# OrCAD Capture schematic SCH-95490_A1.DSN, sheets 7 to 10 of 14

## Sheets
7 07 MCU_LINK: size C
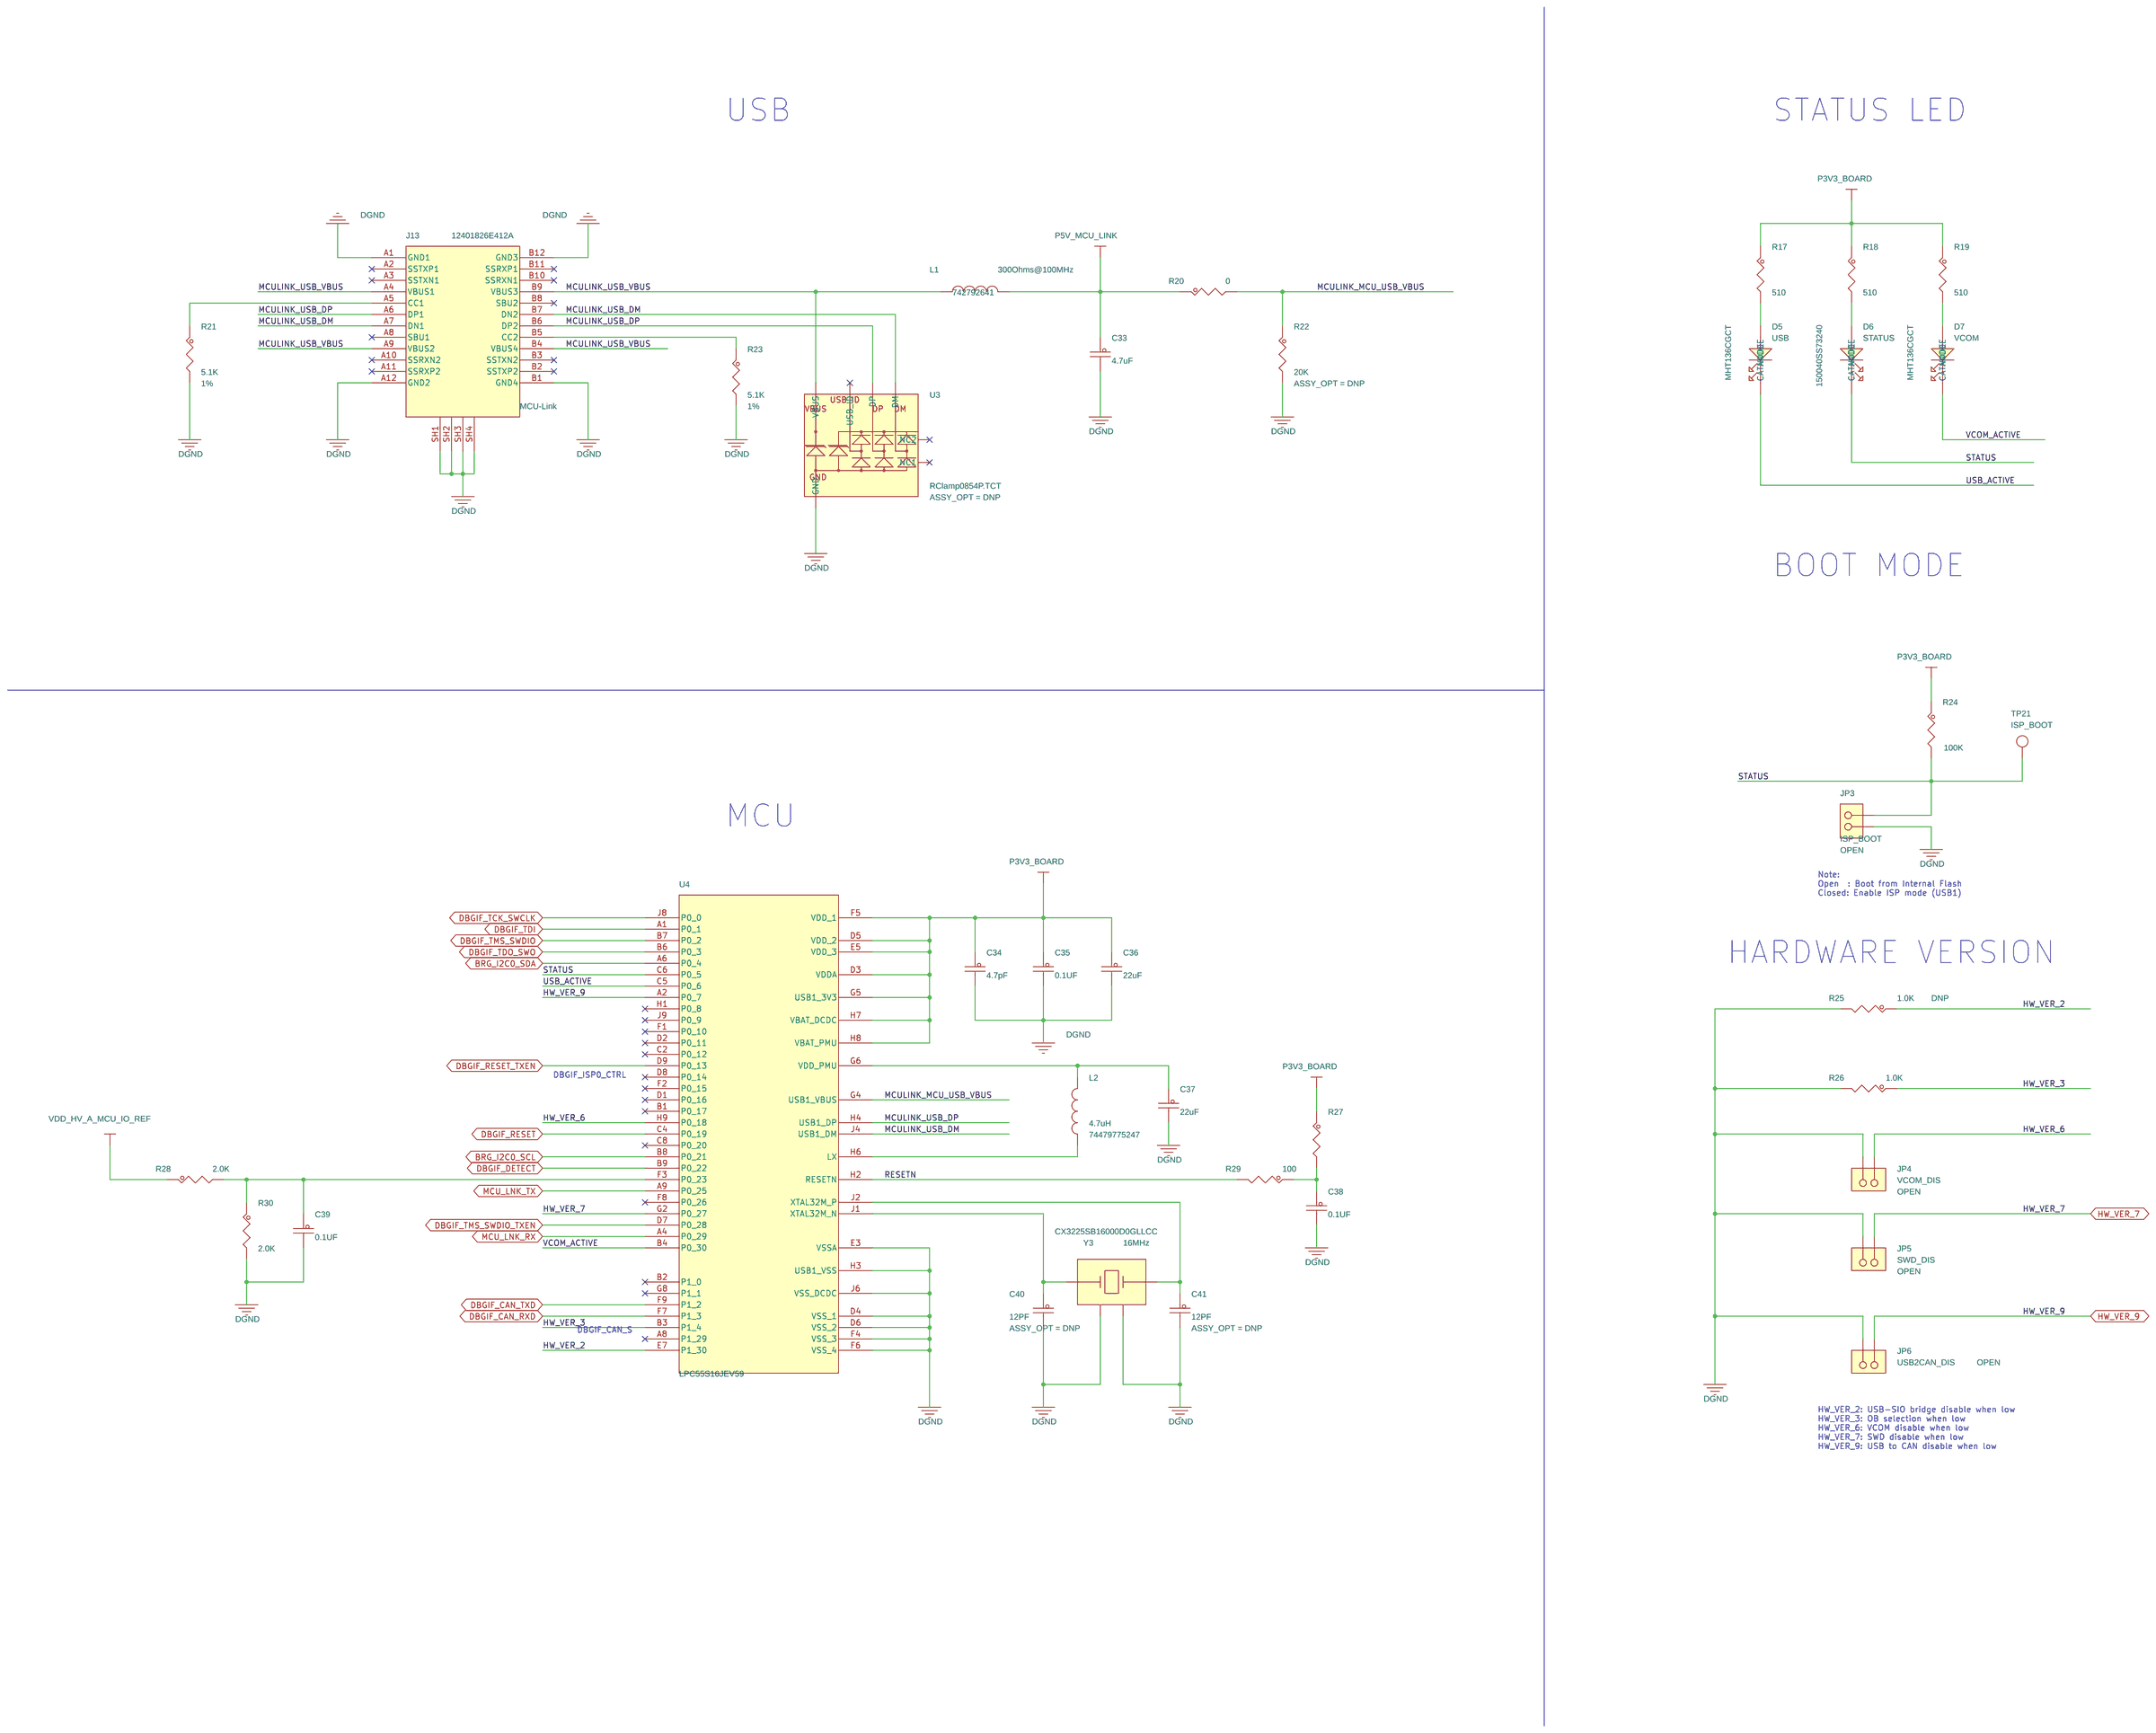
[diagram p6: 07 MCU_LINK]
8 08 MCU_LINK_DEBUG: size C
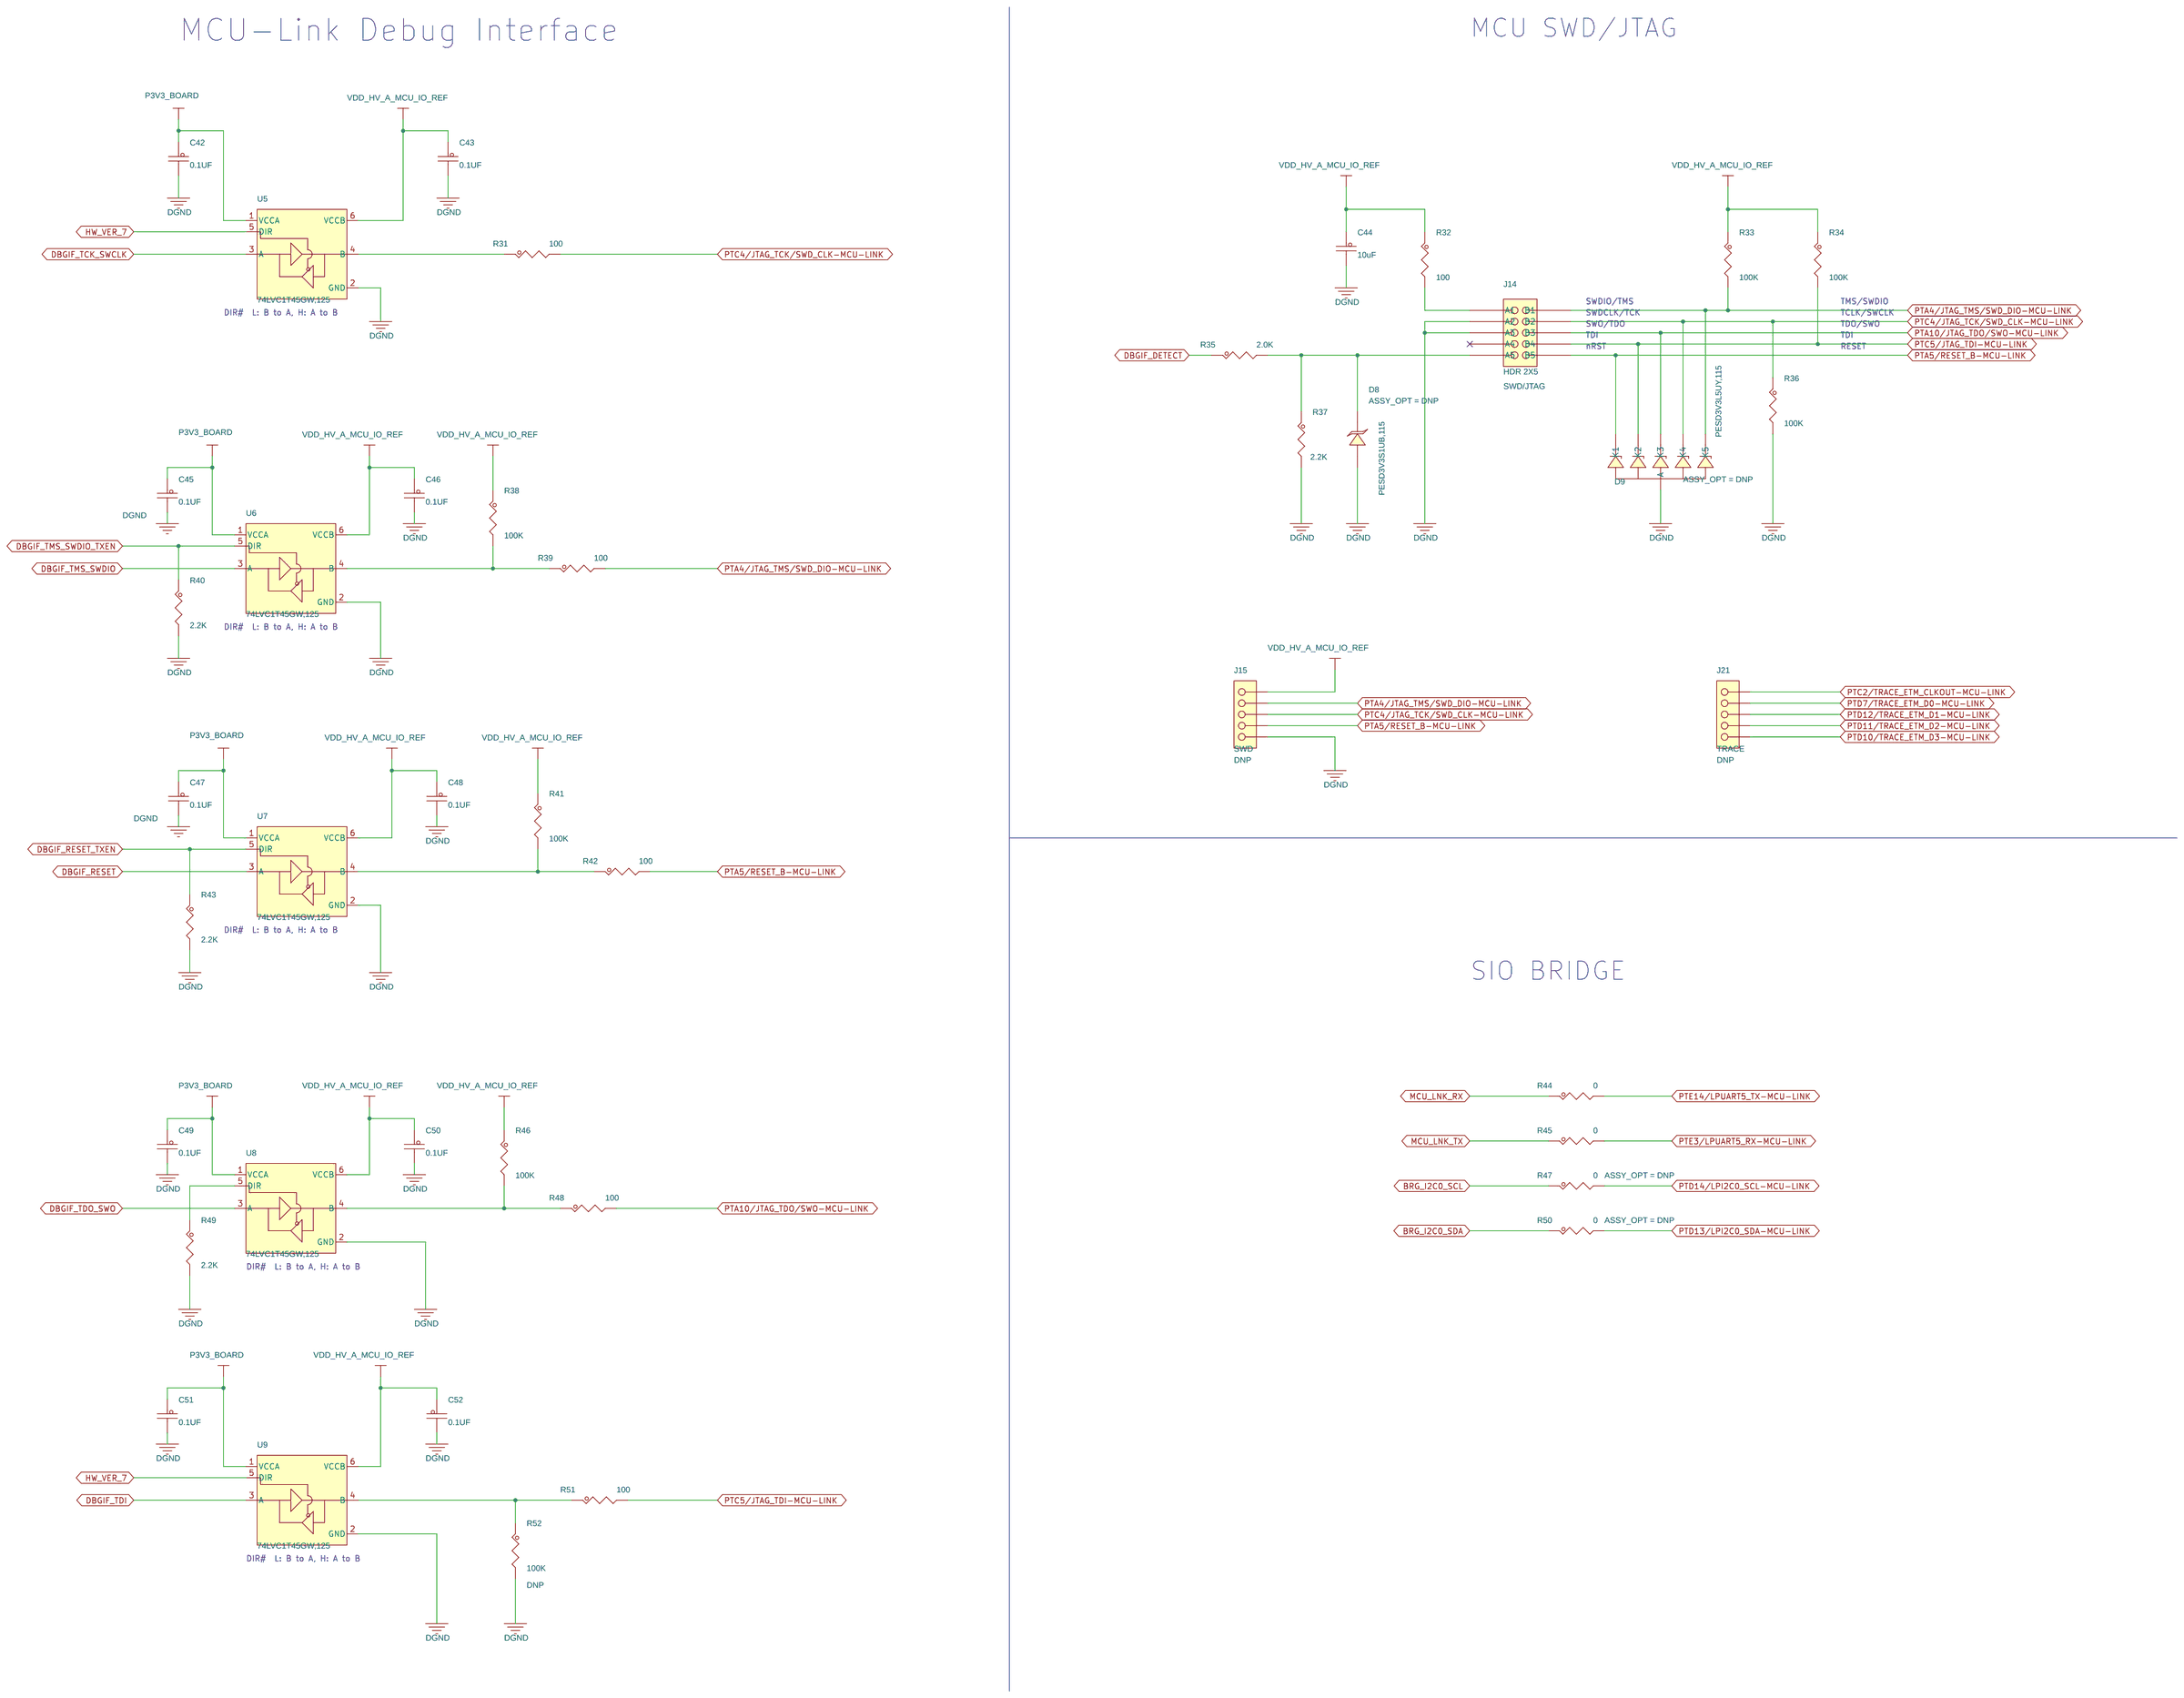
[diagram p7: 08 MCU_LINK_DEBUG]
9 09 ETHERNET: size C
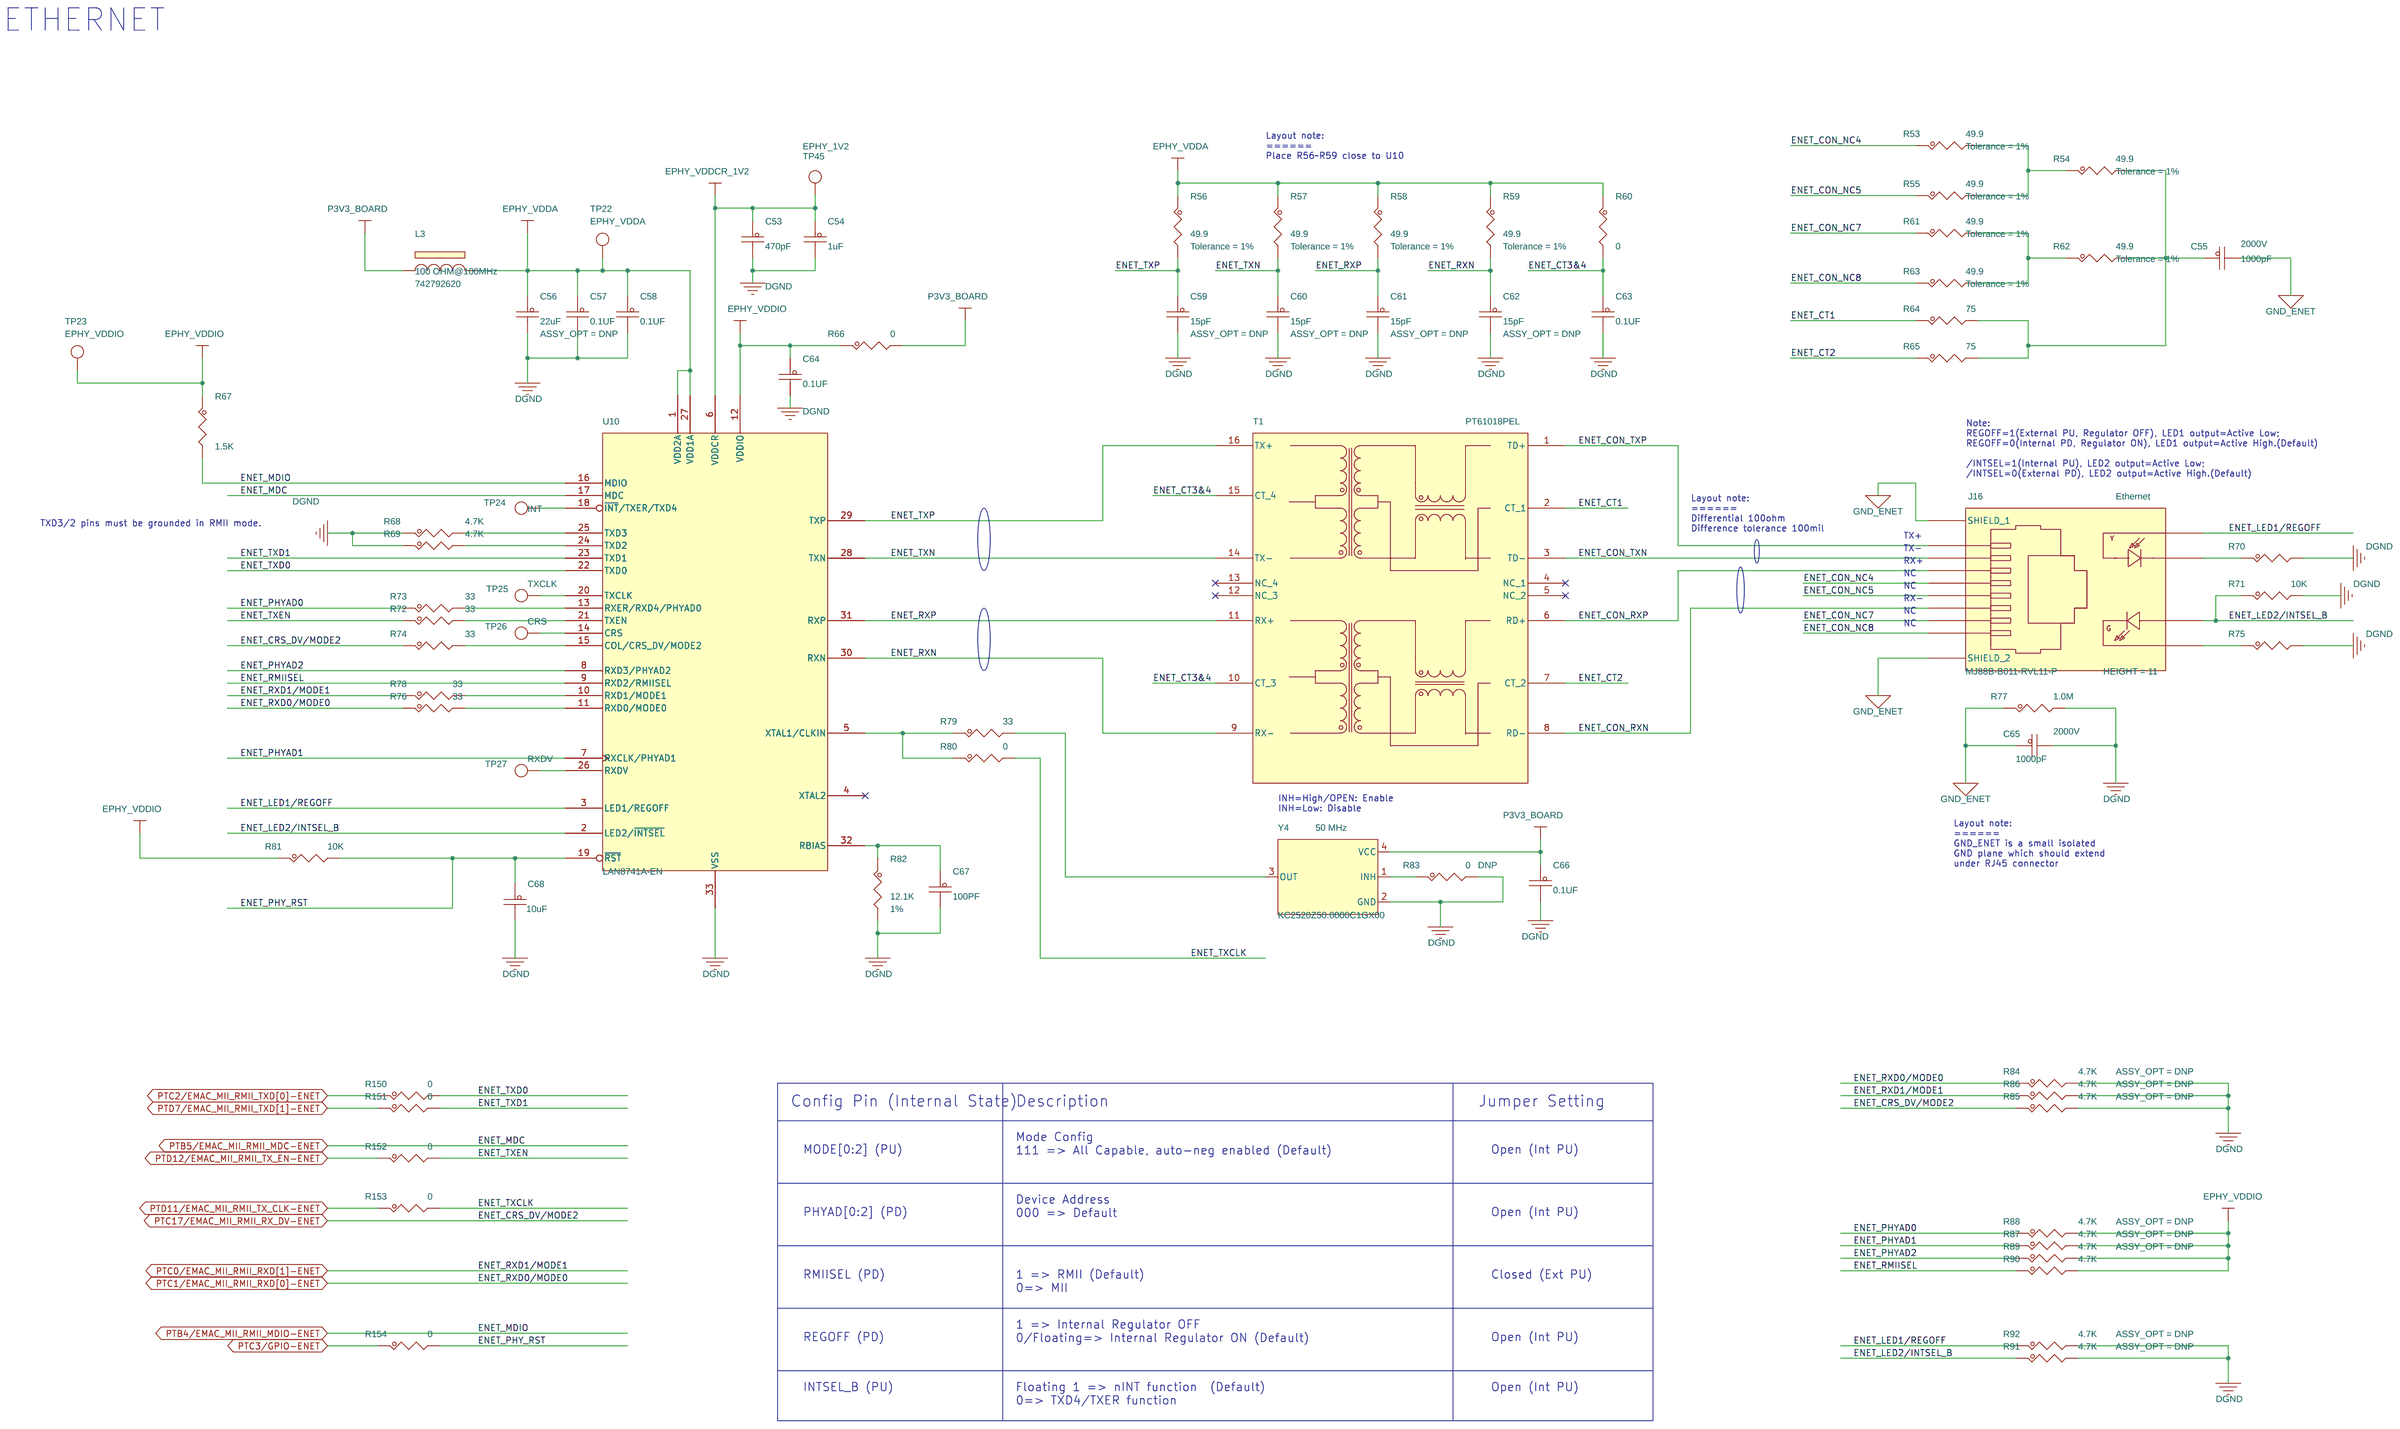
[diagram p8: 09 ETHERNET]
10 10 CAN: size C
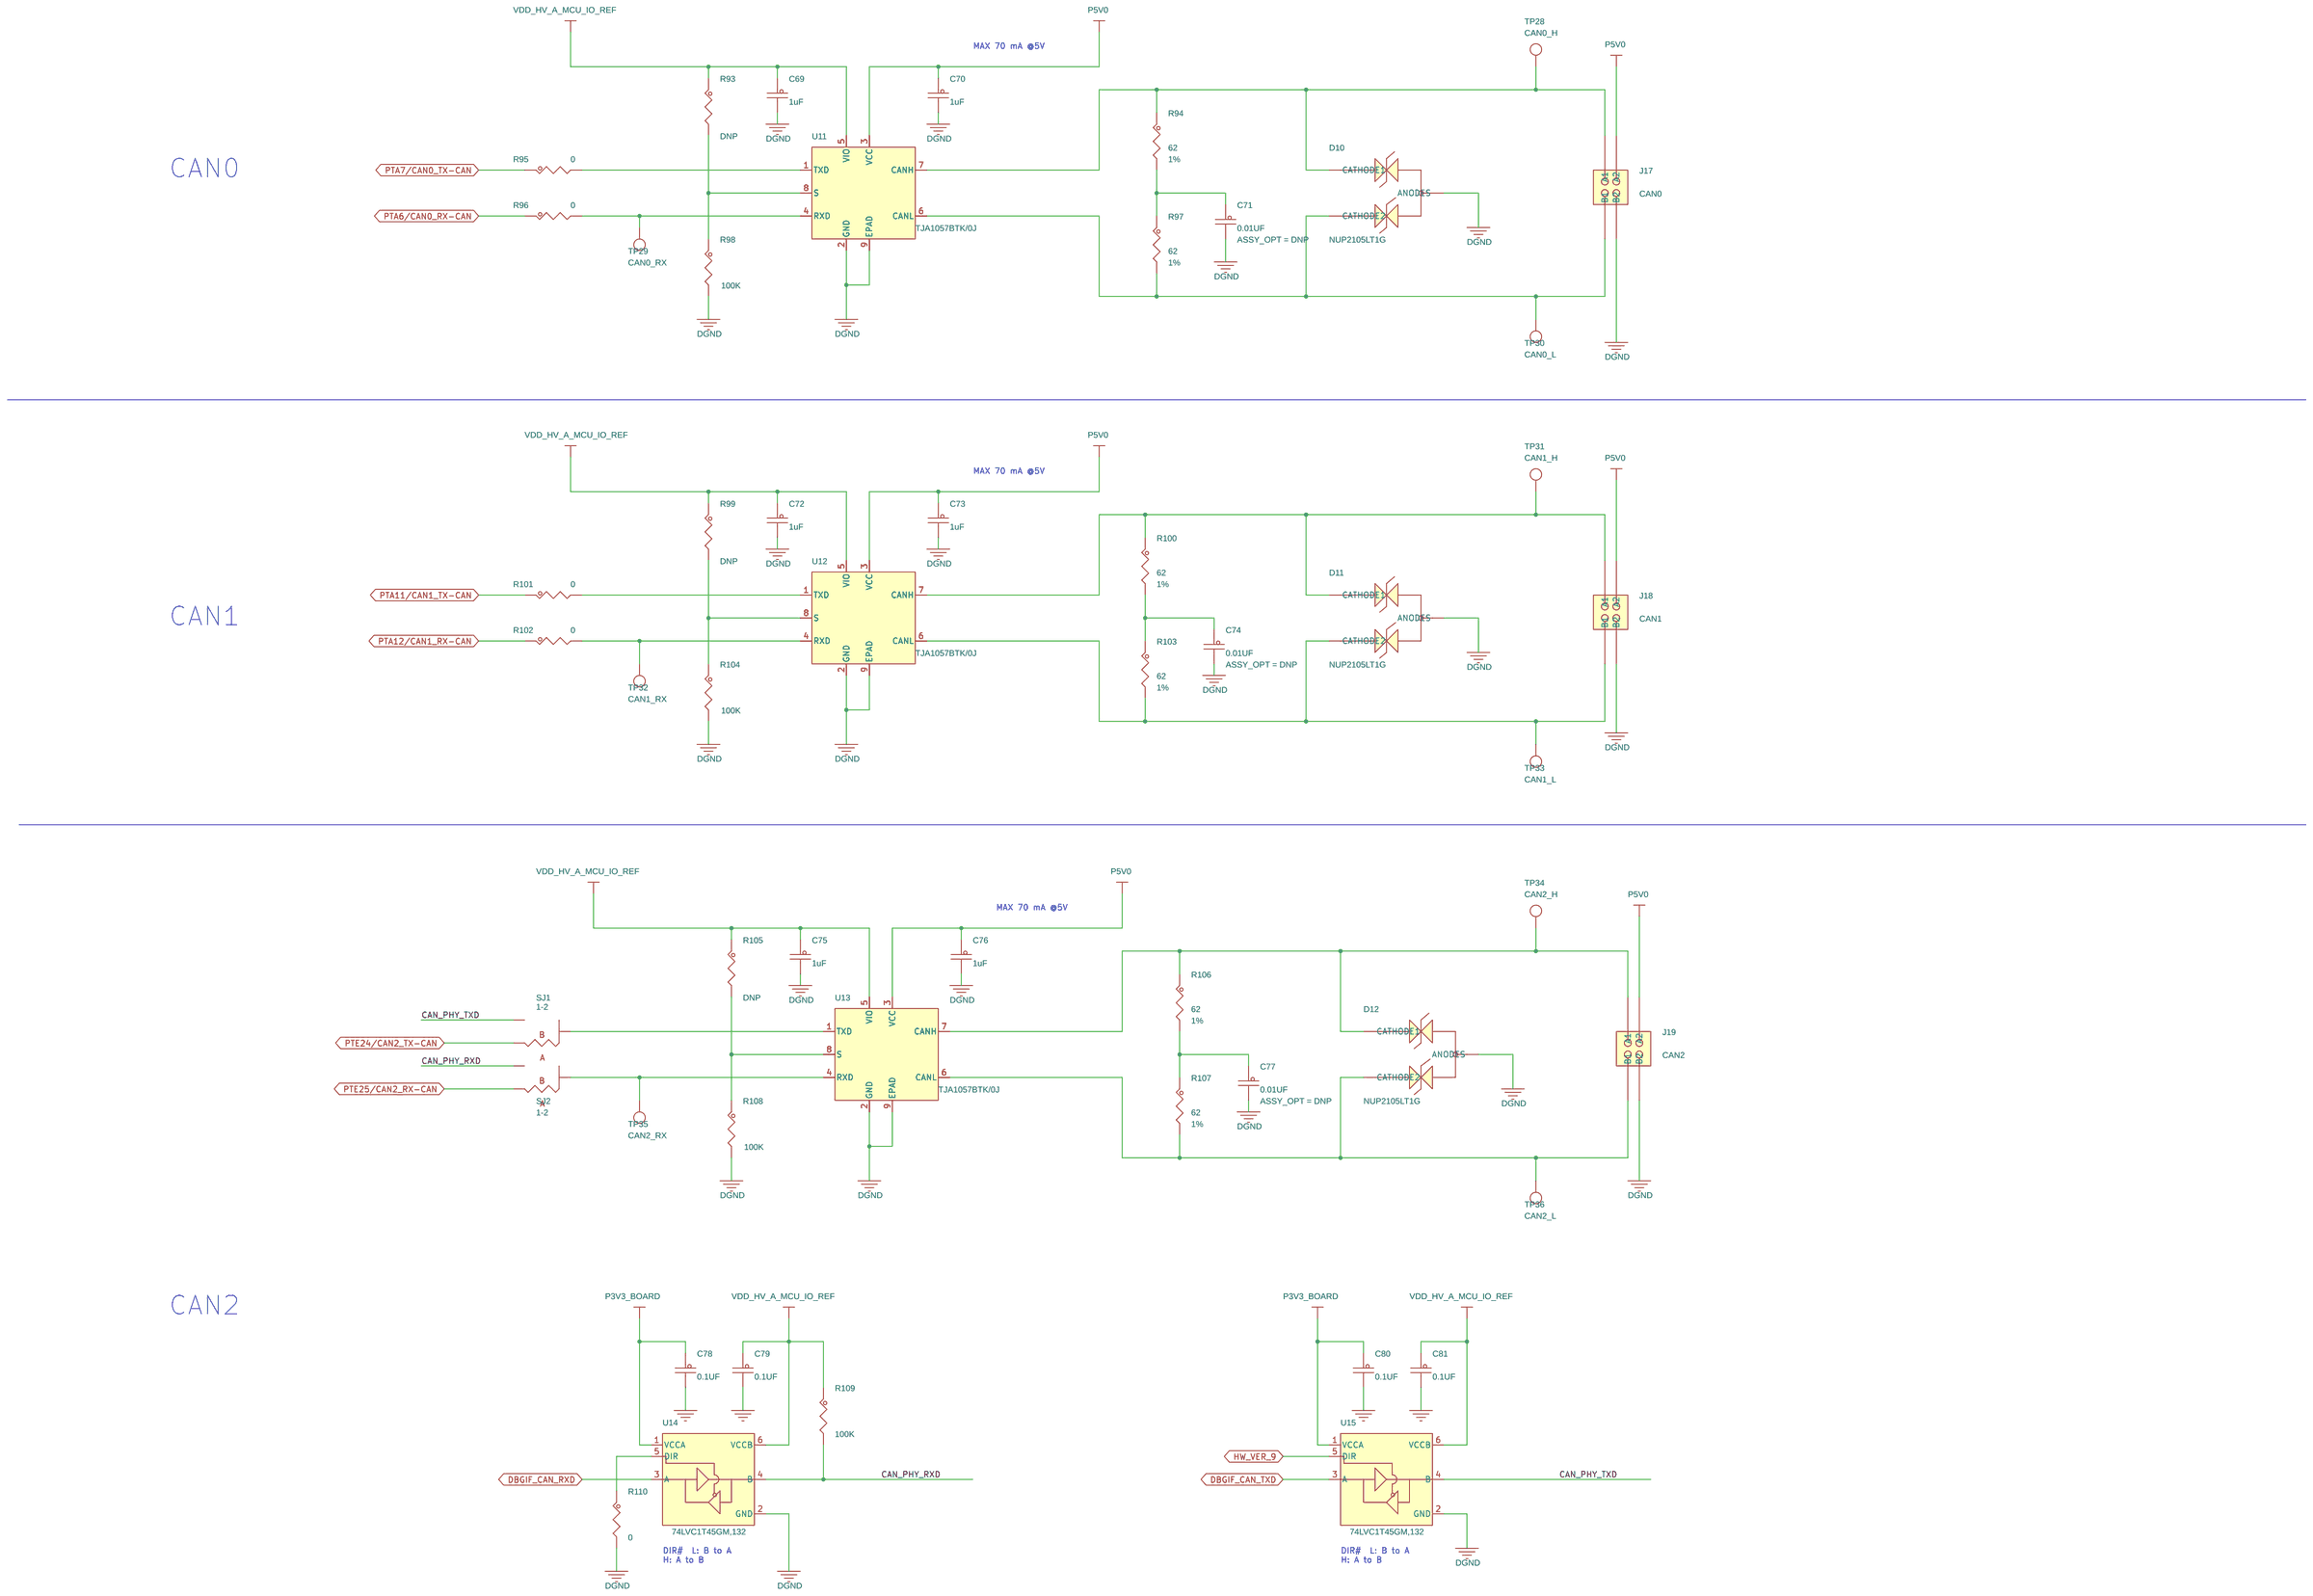
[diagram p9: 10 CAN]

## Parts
sheet 07 MCU_LINK
C33  4.7uF  [CC0603_OV]
C34  4.7pF  [CC0402_25]
C35  0.1UF  [CC0402_25]
C36  22uF  [CC0603_OV]
C37  22uF  [CC0603_OV]
C38  0.1UF  [CC0402_25]
C39  0.1UF  [CC0402_25]
C40  12PF  [CC0402_25]
C41  12PF  [CC0402_25]
D5  YEL-GRN  [led_1x0p6_sm]
D6  RED LED  [led_1p1_1p1x0p6_sm]
D7  YEL-GRN  [led_1x0p6_sm]
J13  USB_TYPE_C  [usb24_type_c_10p5x9p18mm_ra_smt]
JP3  HDR1X2  [hdr1x2_5p48x2p69]
JP4  HDR1X2  [hdr1x2_5p48x2p69]
JP5  HDR1X2  [hdr1x2_5p48x2p69]
JP6  HDR1X2  [hdr1x2_5p48x2p69]
L1  300Ohms@100MHz  [ind_1p8x1mm_sm]
L2  4.7uH  [ind_2p3x1p4_1_sm]
R17  510  [RC0402_25]
R18  510  [RC0402_25]
R19  510  [RC0402_25]
R20  0  [RC0603_OV]
R21  5.1K  [RC0402_25]
R22  20K  [RC0402_25]
R23  5.1K  [RC0402_25]
R24  100K  [RC0402_25]
R25  1.0K  [RC0402_25]
R26  1.0K  [RC0402_25]
R27  10K  [RC0402_25]
R28  2.0K  [RC0402_25]
R29  100  [RC0402_25]
R30  2.0K  [RC0402_25]
TP21  TEST POINT  [tpad_040-fct]
U3  RClamp0854P.TCT  [slp1616p6]
U4  LPC55S16JEV59  [pbga59_0p4_4x4mm]
Y3  16MHz  [xtal4_cx3225ca_sm]
sheet 08 MCU_LINK_DEBUG
C42  0.1UF  [CC0402_25]
C43  0.1UF  [CC0402_25]
C44  10uF  [CC0603_OV]
C45  0.1UF  [CC0402_25]
C46  0.1UF  [CC0402_25]
C47  0.1UF  [CC0402_25]
C48  0.1UF  [CC0402_25]
C49  0.1UF  [CC0402_25]
C50  0.1UF  [CC0402_25]
C51  0.1UF  [CC0402_25]
C52  0.1UF  [CC0402_25]
D8  PESD3V3S1UB  [sod523]
D9  PESD3V3L5UY  [sot-363_0p65_smt]
J14  HDR 2X5  [hdr_5x2_ftsh_th_nsp_a]
J15  HDR_1X5  [con1x5_2p54_th_ra]
J21  HDR 1X5  [hdr1x5_2p54_2p7x12p9_th]
R31  100  [RC0402_25]
R32  100  [RC0402_25]
R33  100K  [RC0402_25]
R34  100K  [RC0402_25]
R35  2.0K  [RC0402_25]
R36  100K  [RC0402_25]
R37  2.2K  [RC0402_25]
R38  100K  [RC0402_25]
R39  100  [RC0402_25]
R40  2.2K  [RC0402_25]
R41  100K  [RC0402_25]
R42  100  [RC0402_25]
R43  2.2K  [RC0402_25]
R44  0  [RC0603_OV]
R45  0  [RC0603_OV]
R46  100K  [RC0402_25]
R47  0  [RC0603_OV]
R48  100  [RC0402_25]
R49  2.2K  [RC0402_25]
R50  0  [RC0603_OV]
R51  100  [RC0402_25]
R52  100K  [RC0402_25]
U5  74LVC1T45GW,125  [SOT-363_0P65_SMT]
U6  74LVC1T45GW,125  [SOT-363_0P65_SMT]
U7  74LVC1T45GW,125  [SOT-363_0P65_SMT]
U8  74LVC1T45GW,125  [SOT-363_0P65_SMT]
U9  74LVC1T45GW,125  [SOT-363_0P65_SMT]
sheet 09 ETHERNET
C53  470pF  [CC0402_25]
C54  1uF  [CC0402_25]
C55  1000pF  [CC1206_OV]
C56  22uF  [CC0603_OV]
C57  0.1UF  [CC0402_25]
C58  0.1UF  [CC0402_25]
C59  15pF  [CC0402_25]
C60  15pF  [CC0402_25]
C61  15pF  [CC0402_25]
C62  15pF  [CC0402_25]
C63  0.1UF  [CC0402_25]
C64  0.1UF  [CC0402_25]
C65  1000pF  [CC1206_OV]
C66  0.1UF  [CC0402_25]
C67  100PF  [CC0402_25]
C68  10uF  [CC0603_OV]
J16  RJ45X2_LEDYG  [con12p_1p02_16p48x15p5_ra_th]
L3  100 OHM@100MHz  [ind_1p8x1mm_sm]
R53  49.9  [RC0402_25]
R54  49.9  [RC0402_25]
R55  49.9  [RC0402_25]
R56  49.9  [RC0402_25]
R57  49.9  [RC0402_25]
R58  49.9  [RC0402_25]
R59  49.9  [RC0402_25]
R60  0  [RC0603_OV]
R61  49.9  [RC0402_25]
R62  49.9  [RC0402_25]
R63  49.9  [RC0402_25]
R64  75  [RC0402_25]
R65  75  [RC0402_25]
R66  0  [RC0603_OV]
R67  1.5K  [RC0402_25]
R68  4.7K  [RC0402_25]
R69  4.7K  [RC0402_25]
R70  470  [RC0402_25]
R71  10K  [RC0402_25]
R72  33  [RC0402_25]
R73  33  [RC0402_25]
R74  33  [RC0402_25]
R75  470  [RC0402_25]
R76  33  [RC0402_25]
R77  1.0M  [RC0805_OV]
R78  33  [RC0402_25]
R79  33  [RC0402_25]
R80  0  [RC0603_OV]
R81  10K  [RC0402_25]
R82  12.1K  [RC0402_25]
R83  0  [RC0603_OV]
R84  4.7K  [RC0402_25]
R85  4.7K  [RC0402_25]
R86  4.7K  [RC0402_25]
R87  4.7K  [RC0402_25]
R88  4.7K  [RC0402_25]
R89  4.7K  [RC0402_25]
R90  4.7K  [RC0402_25]
R91  4.7K  [RC0402_25]
R92  4.7K  [RC0402_25]
R150  0  [RC0603_OV]
R151  0  [RC0603_OV]
R152  0  [RC0603_OV]
R153  0  [RC0603_OV]
R154  0  [RC0603_OV]
T1  PT61018PEL  [xfmr16_1p27_13p05x7p15]
TP22  TEST POINT  [tpad_040-fct]
TP23  TEST POINT  [tpad_040-fct]
TP24  TPAD_030  [TPAD_030]
TP25  TPAD_030  [TPAD_030]
TP26  TPAD_030  [TPAD_030]
TP27  TPAD_030  [TPAD_030]
TP45  TEST POINT  [tpad_040-fct]
U10  LAN8741A-EN  [QFN32EP]
Y4  50 MHz  [osc4_2p6x2p1_sm]
sheet 10 CAN
C69  1uF  [CC0402_25]
C70  1uF  [CC0402_25]
C71  0.01UF  [CC0402_25]
C72  1uF  [CC0402_25]
C73  1uF  [CC0402_25]
C74  0.01UF  [CC0402_25]
C75  1uF  [CC0402_25]
C76  1uF  [CC0402_25]
C77  0.01UF  [CC0402_25]
C78  0.1UF  [CC0402_25]
C79  0.1UF  [CC0402_25]
C80  0.1UF  [CC0402_25]
C81  0.1UF  [CC0402_25]
D10  NUP2105L  [sot-23]
D11  NUP2105L  [sot-23]
D12  NUP2105L  [sot-23]
J17  HDR 2X2  [hdr202_100_th]
J18  HDR 2X2  [hdr202_100_th]
J19  HDR 2X2  [hdr202_100_th]
R93  10K  [RC0402_25]
R94  62  [RC0805_OV]
R95  0  [RC0603_OV]
R96  0  [RC0603_OV]
R97  62  [RC0805_OV]
R98  100K  [RC0402_25]
R99  10K  [RC0402_25]
R100  62  [RC0805_OV]
R101  0  [RC0603_OV]
R102  0  [RC0603_OV]
R103  62  [RC0805_OV]
R104  100K  [RC0402_25]
R105  10K  [RC0402_25]
R106  62  [RC0805_OV]
R107  62  [RC0805_OV]
R108  100K  [RC0402_25]
R109  100K  [RC0402_25]
R110  0  [RC0603_OV]
SJ1  3 PIN 0402 JUMPER  [3pin_0402x2_a]
SJ2  3 PIN 0402 JUMPER  [3pin_0402x2_a]
TP28  TEST POINT  [tpad_040-fct]
TP29  TPAD_030  [TPAD_030]
TP30  TEST POINT  [tpad_040-fct]
TP31  TEST POINT  [tpad_040-fct]
TP32  TPAD_030  [TPAD_030]
TP33  TEST POINT  [tpad_040-fct]
TP34  TEST POINT  [tpad_040-fct]
TP35  TPAD_030  [TPAD_030]
TP36  TEST POINT  [tpad_040-fct]
U11  TJA1057BTK  [son8_0p65_3p15x3p15]
U12  TJA1057BTK  [son8_0p65_3p15x3p15]
U13  TJA1057BTK  [son8_0p65_3p15x3p15]
U14  74LVC1T45GM,132  [udfn6_1x1p5mm]
U15  74LVC1T45GM,132  [udfn6_1x1p5mm]

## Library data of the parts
C33 = CAP_NP: CAP CER 4.7uF 10V 20% X5R 0603; 3D_Mechanical_Footprint_File: http://fcl.am.freescale.net/ALLEGRO/step/cc0603_ov.STEP; AGILE_PN: 150-81893; CAD_APPROVED: Yes; FPLIST: CC0603_OV,CC0603,0603_CC; HEIGHT: 0.87; MFG_NAME01: WURTH ELEKTRONIK; MFG_PN01: 885012106012; Package Size: 0603; Package Type: WCAP-CSGP_0603; ROHS: Yes; ROOM: CPU; Rated Voltage: 10V; SIGNAL_MODEL: DEFAULT_CAPACITOR_220000pF_2_1; TOL: 10%; Temp Range: -55C TO 85C; Tolerance: 20%; VOLTAGE: 10V; WVDC: 10V
C34 = CAP_NP: CAP CER 4.7PF 50V 0.5pF C0G 0402; AGILE_PN: 150-80750; CAD_APPROVED: yes; FPLIST: CC0402_25,CC0402_HD,0402_CC,capc0402_l; HEIGHT: 0.5; MFG_NAME01: Wurth Elektronik; MFG_PN01: 885012005053; Package Size: 0402 (1005 metric); Package Type: SMD/SMT; ROHS: yes; Rated Voltage: 50V; Temp Range: -55C to +125C; Tolerance: 0.5pF
C35 C38 C57 C58 C63 C64 C66 = CAP_NP: CAP CER 0.1UF 16V 10% X7R 0402; 3D_Mechanical_Footprint_File: http://fcl.am.freescale.net/ALLEGRO/step/cc0402_25.STEP; AGILE_PN: 150-75182; CAD_APPROVED: Yes; FPLIST: CC0402_25,CC0402_HD,0402_CC,CAPC0402_L,cc0402_lamp3; HEIGHT: 0.635mm; MFG_NAME01: Samsung Electro-Mechanics; MFG_PN01: CL05B104KO5NNNC; ROHS: NULL; Rated Voltage: 16V; SIGNAL_MODEL: DEFAULT_CAPACITOR_100000pF_2_1; TOL: 10%; Temp Range: -55C to +125C; Temp_Range: -55°C to +85°C; Tolerance: 10%; VOLTAGE: 16V
C36 = CAP_NP: CAP CER 22uF 10V 20% X5R 0603; 3D_Mechanical_Footprint_File: http://fcl.am.freescale.net/ALLEGRO/step/cc0603_ov.STEP; AGILE_PN: 150-79530; CAD_APPROVED: Yes; FPLIST: CC0603_OV,CC0603; HEIGHT: 1.05mm; MFG_NAME01: SAMSUNG; MFG_PN01: CL10A226MP7LUNC; Package Size: 0603 [1608 Metric]; Package Type: SMD/SMT; ROHS: NULL; Rated Voltage: 10V; Temp Range: -55°C to 85°C; Tolerance: 20%; VOLTAGE: 10V
C37 = CAP_NP: CAP CER 22uF 10V 20% X5R 0603; 3D_Mechanical_Footprint_File: http://fcl.am.freescale.net/ALLEGRO/step/cc0603_ov.STEP; AGILE_PN: 150-79530; CAD_APPROVED: Yes; FPLIST: CC0603_OV,CC0603,0603_cc_tol; HEIGHT: 1.05mm; MFG_NAME01: SAMSUNG; MFG_PN01: CL10A226MP7LUNC; Package Size: 0603 [1608 Metric]; Package Type: SMD/SMT; ROHS: NULL; Rated Voltage: 10V; Temp Range: -55°C to 85°C; Tolerance: 20%
C39 = CAP_NP: CAP CER 0.1UF 16V 10% X7R 0402; 3D_Mechanical_Footprint_File: http://fcl.am.freescale.net/ALLEGRO/step/cc0402_25.STEP; AGILE_PN: 150-75182; CAD_APPROVED: Yes; FPLIST: CC0402_25,CC0402_HD,0402_CC,CAPC0402_L,cc0402_lamp3; HEIGHT: 0.635mm; MFG_NAME01: Samsung Electro-Mechanics; MFG_PN01: CL05B104KO5NNNC; ROHS: NULL; Rated Voltage: 16V; Temp Range: -55C to +125C; Tolerance: 10%
C40 C41 = CAP_NP: CAP CER 12PF 25V 5% C0G 0402; AGILE_PN: 150-30180; ASSY_OPT: DNP; CAD_APPROVED: Yes; FPLIST: CC0402_25,CC0402_HD,0402_CC,capc0402_l; HEIGHT: 0.55; MFG_NAME01: KEMET; MFG_PN01: C0402C120J3GAC7867; ROHS: Yes; Rated Voltage: 25V; Temp Range: -55C to +125C; Tolerance: 5%
D5 = LED: LED YEL-GRN SGL 25mA SMT 0402; 3D_Mechanical_Footprint_File: http://fcl.am.freescale.net/ALLEGRO/step/led_1x0p6_sm_14h.step; AGILE_PN: 370-76900; CAD_APPROVED: YES; HEIGHT: 0.35mm; MFG_NAME01: Lianyungang Meihua Electronics Technology Co.,Ltd; MFG_PN01: MHT136CGCT; Package Size: 1 x 0.5 x 0.3 mm; Rated Voltage: 1.7-2.2V@5mA; SILK: USB; Temp Range: -35°C to +85°C; VOLTAGE: 1.7-2.2V@5mA
D6 = LED: LED RED SGL 30mA 5V 0402; 3D_Mechanical_Footprint_File: http://fcl.am.freescale.net/ALLEGRO/step/led_1p1_1p1x0p6_sm.STEP; AGILE_PN: 370-77428; CAD_APPROVED: YES; HEIGHT: 0.5; MFG_NAME01: Wurth Electronik GmbH & Co. KG (PCB); MFG_PN01: 150040SS73240; SILK: STATUS; Temp Range: -40° C to + 85° C
D7 = LED: LED YEL-GRN SGL 25mA SMT 0402; 3D_Mechanical_Footprint_File: http://fcl.am.freescale.net/ALLEGRO/step/led_1x0p6_sm_14h.step; AGILE_PN: 370-76900; CAD_APPROVED: YES; HEIGHT: 0.35mm; MFG_NAME01: Lianyungang Meihua Electronics Technology Co.,Ltd; MFG_PN01: MHT136CGCT; Package Size: 1 x 0.5 x 0.3 mm; Rated Voltage: 1.7-2.2V@5mA; SILK: VCOM; Temp Range: -35°C to +85°C; VOLTAGE: 1.7-2.2V@5mA
J13 = USB24_TYPEC: CON 24 USB_TYPE_C 3.2 SMT RA SHLD SKT SMT 0.5MM SP 135H AU; 3D_Mechanical_Footprint_File: http://fcl.am.freescale.net/ALLEGRO/step/usb24_type_c_10p5x9p18mm_ra_smt.STEP; AGILE_PN: 211-10168; CAD_APPROVED: Yes; HEIGHT: 3.43MM; MFG_NAME01: AMPHENOL; MFG_PN01: 12401826E412A; Package Type: Surface Mount, Right Angle; Through Hole; ROHS: NULL; SILK: MCU-Link; Temp Range: -20C to +85C
JP3 = CONN_HDR_2X1: HDR 1X2 TH 100MIL SP 342H AU 118L; 3D_Mechanical_Footprint_File: http://fcl.am.freescale.net/ALLEGRO/step/hdr1x2_5p48x2p69.STEP; AGILE_PN: 210-80468; CAD_APPROVED: Yes; HEIGHT: 8.69; JUMPER: OPEN; MFG_NAME01: WURTH ELEKTRONIK EISOS GMBH & CO. KG (ELECTRONIC & ELECTROMEHANICAL COMP); MFG_PN01: 61300211121; Package Type: TH; ROHS: Yes; SILK: ISP_BOOT; Temp Range: -40°C to 105°C
JP4 = CONN_HDR_2X1: HDR 1X2 TH 100MIL SP 342H AU 118L; 3D_Mechanical_Footprint_File: http://fcl.am.freescale.net/ALLEGRO/step/hdr1x2_5p48x2p69.STEP; AGILE_PN: 210-80468; CAD_APPROVED: Yes; HEIGHT: 8.69; JUMPER: OPEN; MFG_NAME01: WURTH ELEKTRONIK EISOS GMBH & CO. KG (ELECTRONIC & ELECTROMEHANICAL COMP); MFG_PN01: 61300211121; Package Type: TH; ROHS: Yes; SILK: VCOM_DIS; Temp Range: -40°C to 105°C
JP5 = CONN_HDR_2X1: HDR 1X2 TH 100MIL SP 342H AU 118L; 3D_Mechanical_Footprint_File: http://fcl.am.freescale.net/ALLEGRO/step/hdr1x2_5p48x2p69.STEP; AGILE_PN: 210-80468; CAD_APPROVED: Yes; HEIGHT: 8.69; JUMPER: OPEN; MFG_NAME01: WURTH ELEKTRONIK EISOS GMBH & CO. KG (ELECTRONIC & ELECTROMEHANICAL COMP); MFG_PN01: 61300211121; Package Type: TH; ROHS: Yes; SILK: SWD_DIS; Temp Range: -40°C to 105°C
JP6 = CONN_HDR_2X1: HDR 1X2 TH 100MIL SP 342H AU 118L; 3D_Mechanical_Footprint_File: http://fcl.am.freescale.net/ALLEGRO/step/hdr1x2_5p48x2p69.STEP; AGILE_PN: 210-80468; CAD_APPROVED: Yes; HEIGHT: 8.69; JUMPER: OPEN; MFG_NAME01: WURTH ELEKTRONIK EISOS GMBH & CO. KG (ELECTRONIC & ELECTROMEHANICAL COMP); MFG_PN01: 61300211121; Package Type: TH; ROHS: Yes; SILK: USB2CAN_DIS; Temp Range: -40°C to 105°C
L1 = INDUCTOR: IND FER BEAD 300Ohms@100MHz 2A 25% 0603; 3D_Mechanical_Footprint_File: http://fcl.am.freescale.net/ALLEGRO/step/ind_1p8x1mm_sm.step; AGILE_PN: 180-78959; CAD_APPROVED: Yes; HEIGHT: 1; MFG_NAME01: WURTH ELEKTRONIK EISOS GMBH & CO. KG (ELECTRONIC & ELECTROMEHANICAL COMP); MFG_PN01: 742792641; Package Size: 0603; ROHS: Yes; Temp Range: -55°C to 125°C
L2 = INDUCTOR: IND PWR 4.7uH@1MHz 0.85A 0.25OHM 20% SMT; 3D_Mechanical_Footprint_File: http://fcl.am.freescale.net/ALLEGRO/step/ind_2p3x1p4_1_sm.STEP; AGILE_PN: 180-80000; CAD_APPROVED: YES; HEIGHT: 1; MFG_NAME01: WURTH ELEKTRONIK EISOS GMBH & CO. KG (ELECTRONIC & ELECTROMEHANICAL COMP); MFG_PN01: 74479775247; Package Size: 0805; ROHS: Yes; Temp Range: -40C to +125C
R17-R19 = RES: RES 510 OHMS 1/16W 5% RC0402 ROHS; AGILE_PN: 470-76237; CAD_APPROVED: Yes; FPLIST: RC0402_25,RC0402_HD,0402_CC; HEIGHT: 0.4; MFG_NAME01: YAGEO AMERICA; MFG_PN01: RC0402JR-07510RL; ROHS: Yes; Temp_Range: -55C to +155C
R20 R66 R80 R95 R96 R101 R102 R150-R154 = RES: RES MF ZERO OHM 1/10W -- 0603; AGILE_PN: 470-80866; CAD_APPROVED: Yes; FPLIST: RC0603_OV,RC0603,R603-X2,r603-x2_b,0603_CC,IND_0603HP_NSP,CC0603_OV_NSP; HEIGHT: 0.6; MFG_NAME01: VISHAY; MFG_PN01: CRCW06030000Z0EAC; ROHS: NULL; Temp Range: –55 °C to +155 °C
R21 R23 = RES: RES MF 5.1K 1/16W 1% 0402; AGILE_PN: 470-76474; CAD_APPROVED: Yes; FPLIST: RC0402_25,RC0402_HD,0402_CC; HEIGHT: 0.4; MFG_NAME01: THYE MING TECH CO LTD; MFG_PN01: CR02FL6--5K1; ROHS: Yes; Tolerance: 1%
R22 = RES: RES MF 20K 1/16W 1% 0402; AGILE_PN: 470-76103; ASSY_OPT: DNP; CAD_APPROVED: Yes; FPLIST: RC0402_25,RC0402_HD,0402_CC; HEIGHT: 0.4; MFG_NAME01: WALSIN TECHNOLOGY CORP.; MFG_PN01: WR04X2002FTL; ROHS: Yes; Tolerance: 1%
R24 R38 R41 R46 R98 R104 R108 R109 = RES: RES MF 100K 1/16W 1% 0402; AGILE_PN: 470-76240; CAD_APPROVED: Yes; FPLIST: RC0402_25,RC0402_HD,0402_CC; HEIGHT: 0.4; MFG_NAME01: VISHAY INTERTECHNOLOGY; MFG_PN01: CRCW0402100KFKEDC; ROHS: Yes; Tolerance: 1%
R25 = RES: RES MF 1.0K 1/16W 1% 0402; AGILE_PN: 470-76037; ASSY_OPT: DNP; CAD_APPROVED: Yes; FPLIST: RC0402_25,RC0402_HD,RC0402_X2,0402_CC; HEIGHT: 0.4; MFG_NAME01: YAGEO AMERICA; MFG_PN01: RC0402FR-071KL; ROHS: Yes; Tolerance: 1%
R26 = RES: RES MF 1.0K 1/16W 1% 0402; AGILE_PN: 470-76037; CAD_APPROVED: Yes; FPLIST: RC0402_25,RC0402_HD,RC0402_X2,0402_CC; HEIGHT: 0.4; MFG_NAME01: YAGEO AMERICA; MFG_PN01: RC0402FR-071KL; ROHS: Yes; Tolerance: 1%
R27 = RES: RES MF 10K 1/16W 5% 0402; AGILE_PN: 470-75557; CAD_APPROVED: Yes; FPLIST: RC0402_25,RC0402_HD,0402_CC; HEIGHT: 0.4MM; MFG_NAME01: BOURNS; MFG_PN01: CR0402-JW-103GLF; ROHS: NULL; SIGNAL_MODEL: DEFAULT_RESISTOR_10000OHM_2_1; TOL: 5%; Temp_Range: –55 °C to +155 °C; Tolerance: 5%
R28 R30 R35 = RES: RES MF 2.0K 1/16W 1% 0402; 3D_Mechanical_Footprint_File: http://fcl.am.freescale.net/ALLEGRO/step/rc0402_25.STEP; AGILE_PN: 470-75356; CAD_APPROVED: Yes; FPLIST: RC0402_25,RC0402_HD,0402_CC,rc0402_ghwe; HEIGHT: 0.4; MFG_NAME01: BOURNS; MFG_PN01: CR0402-FX-2001GLF; ROHS: Yes; Tolerance: 1%
R29 R31 R32 R39 R42 R48 R51 = RES: RES MF 100 OHM 1/16W 5% 0402; AGILE_PN: 470-75591; CAD_APPROVED: Yes; HEIGHT: 0.45; MFG_NAME01: BOURNS; MFG_PN01: CR0402-JW-101GLF; ROHS: Yes; Tolerance: 5%
TP21 = TESTLOOP: TEST POINT PAD 40MIL DIA SMT, NO PART TO ORDER; AGILE_PN: 211-10189; CAD_APPROVED: yes; HEIGHT: 0.1MM; MFG_NAME01: NO PART TO ORDER; MFG_PN01: NO PART TO ORDER; ROHS: NULL; SILK: ISP_BOOT
U3 = RCLAMP1654P_NEW: DIODE TVS ARRAY 3 5.5V SLP1616P6; 3D_Mechanical_Footprint_File: http://fcl.am.freescale.net/ALLEGRO/step/slp1616p6.step; AGILE_PN: 480-78843; ASSY_OPT: DNP; CAD_APPROVED: Yes; HEIGHT: 0.65mm; MFG_NAME01: SEMTECH CORP; Rated Voltage: 5.5V
U4 = LPC55S1X_PBGA59: IC MCU 32BIT ARM CORTEX-M33 FLASH 256KB SRAM 96KB 1.8-3.6V  VFBGA59; 3D_Mechanical_Footprint_File: http://fcl.am.freescale.net/ALLEGRO/step/pbga59_0p4_4x4mm.step; AGILE_PN: 344-02543; CAD_APPROVED: Yes; HEIGHT: 0.86; MFG_NAME01: NXP SEMICONDUCTOR; ROHS: Yes
Y3 = XTAL_13: XTAL 16MHz 8pF 15PPM 3225 SMT; 3D_Mechanical_Footprint_File: http://fcl.am.freescale.net/ALLEGRO/step/xtal4_cx3225ca_sm.STEP; AGILE_PN: 230-10068; CAD_APPROVED: Yes; Frequency Tolerance: ±15ppm; HEIGHT: 0.6mm; MFG_NAME01: KYOCERA; MFG_PN01: CX3225SB16000D0GLLCC; Package Size: 3.2 mm x 2.5 mm x 0.6 mm; ROHS: NULL; Temp Range: -30C to +85C
C42 C43 C45-C52 C78-C81 = CAP_NP: CAP CER 0.1UF 16V 10% X7R 0402; 3D_Mechanical_Footprint_File: http://fcl.am.freescale.net/ALLEGRO/step/cc0402_25.STEP; AGILE_PN: 150-75182; CAD_APPROVED: Yes; FPLIST: CC0402_25,CC0402_HD,0402_CC,CAPC0402_L,cc0402_lamp3; HEIGHT: 0.635mm; MFG_NAME01: Samsung Electro-Mechanics; MFG_PN01: CL05B104KO5NNNC; ROHS: NULL; Rated Voltage: 16V; Temp Range: -55C to +125C; Temp_Range: -55°C to +125°C; Tolerance: 10%; VOLTAGE: 16V
C44 C68 = CAP_NP: CAP CER 10uF 25V 20% X5R 0603; AGILE_PN: 150-79272; CAD_APPROVED: Yes; FPLIST: CC0603_OV,CC0603,0603_cc_tol; HEIGHT: 1; MFG_NAME01: MURATA; MFG_PN01: GRM188R61E106MA73D; Package Size: 0603; ROHS: Yes; Rated Voltage: 25V; Temp Range: -55C to +85C; Tolerance: 20%
D8 = DIODE_TVS: DIODE TVS UNIDIR 3.3VWM 20VC SOD523; AGILE_PN: 480-79814; ASSY_OPT: DNP; CAD_APPROVED: Yes; HEIGHT: 0.65MM; MFG_NAME01: NEXPERIA; MFG_PN01: PESD3V3S1UB,115; REQUESTED_COMPLETION_DATE: Not an expedite request; ROHS: Yes
D9 = DIODE_ARRAY_5CH: DIODE TVS UNIDIR 3.3VWM 12VC SOT363; AGILE_PN: 480-79841; ASSY_OPT: DNP; CAD_APPROVED: Yes; HEIGHT: 1.1; MFG_NAME01: NEXPERIA; MFG_PN01: PESD3V3L5UY,115; REQUESTED_COMPLETION_DATE: Not an expedite request; ROHS: Yes; Temp Range: -65°C ~ 150°C; Temp_Range: -65°C ~ 150°C
J14 = CONN_HDR_5X2: HDR 2X5 TH 50MIL CTR 172H AU 91L; 3D_Mechanical_Footprint_File: http://fcl.am.freescale.net/ALLEGRO/step/hdr205_50_th_172h.STEP; AGILE_PN: 210-81466; CAD_APPROVED: Yes; FPLIST: hdr205_50_th_172h,hdr205_50_th; HEIGHT: 4.38mm; MFG_NAME01: CNT Electrical Company Ltd; MFG_PN01: CNT-M127-2*5-GS-3/2.3-100; ROHS: NULL; SILK: SWD/JTAG; Temp Range: -55DegC to +105DegC
J15 = CONN_HDR_5X1: HDR 1X5 RA TH 100MIL 108H AU 120L; 3D_Mechanical_Footprint_File: http://fcl.am.freescale.net/ALLEGRO/step/con1x5_2p54_th_ra.STEP; AGILE_PN: 210-10219; ASSY_OPT: DNP; CAD_APPROVED: Yes; HEIGHT: 2.74MM; MFG_NAME01: SULLINS ELECTRONICS CORP; MFG_PN01: PRPC005SGAN-M71RC; Package Type: Through Hole, Right Angle; ROHS: NULL; SILK: SWD; Temp Range: -40° C to + 105° C
J21 = CONN_HDR_5X1: HDR 1X5 TH 100MIL SP 323H AU 130L; 3D_Mechanical_Footprint_File: http://fcl.am.freescale.net/ALLEGRO/step/hdr1x5_2p54_2p7x12p9_th.STEP; AGILE_PN: 210-10015; ASSY_OPT: DNP; CAD_APPROVED: Yes; HEIGHT: 8.2MM; MFG_NAME01: 3M; MFG_PN01: 961105-6404-AR; Package Type: Through Hole; ROHS: NULL; SILK: TRACE; Temp Range: -25°C to +105°C
R33 R34 R36 = RES: RES MF 100K 1/16W 1% 0402; AGILE_PN: 470-76240; CAD_APPROVED: Yes; FPLIST: RC0402_25,RC0402_HD,0402_CC; HEIGHT: 0.4; MFG_NAME01: VISHAY INTERTECHNOLOGY; MFG_PN01: CRCW0402100KFKEDC; ROHS: Yes; TOL: 5%; Temp_Range: -55C to +155C; Tolerance: 1%
R37 R40 R43 R49 = RES: RES MF 2.2K 1/16W 1% 0402; 3D_Mechanical_Footprint_File: http://fcl.am.freescale.net/ALLEGRO/step/rc0402_25.STEP; AGILE_PN: 470-83213; CAD_APPROVED: yes; FPLIST: RC0402_25,RC0402_HD,0402_CC; HEIGHT: 0.4mm; MFG_NAME01: Bourns Inc.; MFG_PN01: CR0402-FX-2201GLF; ROHS: NULL; Temp Range: -55 °C to +155 °C; Temp_Range: -55C to +155C
R44 R45 R60 R110 = RES: RES MF ZERO OHM 1/10W -- 0603; AGILE_PN: 470-80866; CAD_APPROVED: Yes; FPLIST: RC0603_OV,RC0603,R603-X2,r603-x2_b,0603_CC,IND_0603HP_NSP,CC0603_OV_NSP; HEIGHT: 0.6; MFG_NAME01: VISHAY; MFG_PN01: CRCW06030000Z0EAC; ROHS: NULL; Temp Range: –55 °C to +155 °C; VOLTAGE: 1/16W
R47 R50 R83 = RES: RES MF ZERO OHM 1/10W -- 0603; AGILE_PN: 470-80866; ASSY_OPT: DNP; CAD_APPROVED: Yes; FPLIST: RC0603_OV,RC0603,R603-X2,r603-x2_b,0603_CC,IND_0603HP_NSP,CC0603_OV_NSP; HEIGHT: 0.6; MFG_NAME01: VISHAY; MFG_PN01: CRCW06030000Z0EAC; ROHS: NULL; Temp Range: –55 °C to +155 °C
R52 = RES: RES MF 100K 1/16W 1% 0402; AGILE_PN: 470-76240; ASSY_OPT: DNP; CAD_APPROVED: Yes; FPLIST: RC0402_25,RC0402_HD,0402_CC; HEIGHT: 0.4; MFG_NAME01: VISHAY INTERTECHNOLOGY; MFG_PN01: CRCW0402100KFKEDC; ROHS: Yes; Tolerance: 1%
U5-U9 = 74LVCH1T45_6P: IC XCVR XLATING DUAL 3-STATE 1.2- 5.5V TSSOP6; AGILE_PN: 312-81277; CAD_APPROVED: Yes; HEIGHT: 1.1; MFG_NAME01: NEXPERIA; ROHS: Yes; VOLTAGE: 1.2- 5.5V
C53 = CAP_NP: CAP CER 470pF 50V 5% C0G 0402; AGILE_PN: 150-30004; CAD_APPROVED: YES; FPLIST: CC0402_25,CC0402_HD,0402_CC,capc0402_l; HEIGHT: 0.55; MFG_NAME01: MURATA; MFG_PN01: GRM1555C1H471JA01D; Package Size: 0402; ROHS: NULL; Rated Voltage: 50V; Temp Range: -55C to +125C; Tolerance: 5%
C54 = CAP_NP: CAP CER 1.0uF 16V 10% X6S 0402; AGILE_PN: 150-80262; CAD_APPROVED: Yes; FPLIST: CC0402_25,CC0402_HD,0402_CC,capc0402_l; HEIGHT: 0.55; MFG_NAME01: MURATA; MFG_PN01: GRM155C81C105KE11D; ROHS: Yes; Rated Voltage: 16V; Temp Range: -55C to +105C; Tolerance: 10%; VOLTAGE: 16V
C55 C65 = CAP_NP: CAP CER 1000pF 2KV 10% X7R 1206; AGILE_PN: 150-79103; CAD_APPROVED: Yes; FPLIST: CC1206_OV,CC1206,1206_CC; HEIGHT: 1.8; MFG_NAME01: WALSIN TECHNOLOGY CORP.; MFG_PN01: 1206B102K202CT; Package Size: 1206; ROHS: Yes; Rated Voltage: 2000V; Temp Range: -55C to +125C; Tolerance: 10%
C56 = CAP_NP: CAP CER 22uF 10V 20% X5R 0603; 3D_Mechanical_Footprint_File: http://fcl.am.freescale.net/ALLEGRO/step/cc0603_ov.STEP; AGILE_PN: 150-79530; ASSY_OPT: DNP; CAD_APPROVED: Yes; FPLIST: CC0603_OV,CC0603,0603_cc_tol; HEIGHT: 1.05mm; MFG_NAME01: SAMSUNG; MFG_PN01: CL10A226MP7LUNC; Package Size: 0603 [1608 Metric]; Package Type: SMD/SMT; ROHS: NULL; Rated Voltage: 10V; Temp Range: -55°C to 85°C; Tolerance: 20%
C59-C62 = CAP_NP: CAP CER 15pF 50V 5% C0G 0402; 3D_Mechanical_Footprint_File: http://fcl.am.freescale.net/ALLEGRO/step/cc0402_25.STEP; AGILE_PN: 150-81667; ASSY_OPT: DNP; CAD_APPROVED: Yes; FPLIST: CC0402_25,CC0402_HD,0402_CC,capc0402_l; HEIGHT: 0.55; MFG_NAME01: Murata Electronics; MFG_PN01: GJM1555C1H150JB01D; Package Size: 0402 (1005 Metric); Package Type: Surface Mount, MLCC; ROHS: Yes; Rated Voltage: 50V; Temp Range: -55°C ~ 125°C; Tolerance: 5%
C67 = CAP_NP: CAP CER 100pF 16V 10% X7R 0402; AGILE_PN: 150-79188; CAD_APPROVED: Yes; FPLIST: CC0402_25,CC0402_HD,0402_CC,capc0402_l; HEIGHT: 0.56; MFG_NAME01: AVX; MFG_PN01: 0402YC101KAT2A; Package Size: 0402; Package Type: 7" Reel; ROHS: Yes; Rated Voltage: 16V; Temp Range: -55C to +125C; Tolerance: 10%
J16 = CON_RJ45_1X8_YG: CON 8 RJ-45 SHLD RA TH YG LEDS 40MIL SP 47H AU 79L; 3D_Mechanical_Footprint_File: http://fcl.am.freescale.net/ALLEGRO/step/con12p_1p02_16p48x15p5_ra_th.STEP; AGILE_PN: 210-83436; CAD_APPROVED: Yes; HEIGHT: 11; MFG_NAME01: Donguan Heling Electronic Co., LTD; MFG_PN01: MJ88B-B011-RVL11-P; Package Type: Through Hole; ROHS: NULL; SILK: Ethernet
L3 = INDUCTOR_FERRITE: IND FER BEAD 100 OHM@100MHz 0.5A 25% AEC-Q200 0603; 3D_Mechanical_Footprint_File: http://fcl.am.freescale.net/ALLEGRO/step/ind_1p8x1mm_sm.step; AGILE_PN: 180-10207; CAD_APPROVED: Yes; HEIGHT: 1mm; MFG_NAME01: WURTH ELEKTRONIK EISOS GMBH & CO. KG (ELECTRONIC & ELECTROMEHANICAL COMP); MFG_PN01: 742792620; Package Size: 0603; ROHS: NULL; Temp Range: -55°C to 125°C
R53-R59 R61-R63 = RES: RES MF 49.9 OHM 1/16W 1% 0402; AGILE_PN: 470-75360; CAD_APPROVED: Yes; FPLIST: RC0402_25,RC0402_HD,0402_CC; HEIGHT: 0.4; MFG_NAME01: BOURNS; MFG_PN01: CR0402-FX-49R9GLF; ROHS: Yes; Tolerance: 1%
R64 R65 = RES: RES MF 75.0 OHM 1/10W 1% AEC-Q200 0402; AGILE_PN: 470-30729; CAD_APPROVED: Yes; FPLIST: RC0402_25,RC0402_HD,0402_CC; HEIGHT: 0.40; MFG_NAME01: KOA SPEER; MFG_PN01: RK73H1ETTP75R0F; ROHS: Yes; Temp Range: -55°C to +155°C; Tolerance: 1%
R67 = RES: RES MF 1.5K 1/16W 1% 0402; AGILE_PN: 470-80487; CAD_APPROVED: Yes; FPLIST: RC0402_25,RC0402_HD,0402_CC; HEIGHT: 0.4; MFG_NAME01: BOURNS; MFG_PN01: CR0402-FX-1501GLF; ROHS: Yes; Tolerance: 1%
R68 R69 R90 = RES: RES MF 4.7K 1/16W 5% 0402; AGILE_PN: 470-75626; CAD_APPROVED: Yes; FPLIST: RC0402_25,RC0402_HD,0402_CC,RC0402_X2; HEIGHT: 0.41; MFG_NAME01: BOURNS; MFG_PN01: CR0402-JW-472GLF; Pkg: 0402; ROHS: NULL; Tolerance: 5%
R70 R75 = RES: RES MF 470 OHM 1/16W 5% 0402; AGILE_PN: 470-30315; CAD_APPROVED: Yes; FPLIST: RC0402_25,RC0402_HD,0402_CC; HEIGHT: 0.45; MFG_NAME01: PANASONIC; MFG_PN01: ERJ2GEJ471X; ROHS: Yes; SIGNAL_MODEL: DEFAULT_RESISTOR_430.000000OHM_2_1; TOL: 1%; Temp_Range: -55&#8451; to 155&#8451;; Tolerance: 5%
R71 R81 = RES: RES MF 10K 1/16W 5% 0402; AGILE_PN: 470-75557; CAD_APPROVED: Yes; FPLIST: RC0402_25,RC0402_HD,0402_CC; HEIGHT: 0.4MM; MFG_NAME01: BOURNS; MFG_PN01: CR0402-JW-103GLF; ROHS: NULL; Tolerance: 5%
R72-R74 R76 R78 R79 = RES: RES MF 33.0 OHM 1/16W 1% 0402; AGILE_PN: 470-75790; CAD_APPROVED: Yes; FPLIST: RC0402_25,RC0402_HD,RC0402_X2,0402_CC; HEIGHT: 0.4; MFG_NAME01: VISHAY; MFG_PN01: CRCW040233R0FKEDC; ROHS: Yes; Tolerance: 1%
R77 = RES: RES MF 1.0M 1/8W 5% 0805; AGILE_PN: 470-75494; CAD_APPROVED: Yes; FPLIST: RC0805_OV,RC0805,0805_CC; HEIGHT: 0.6; MFG_NAME01: BOURNS; MFG_PN01: CR0805-JW-105ELF; ROHS: Yes; Tolerance: 5%
R82 = RES: RES MF 12.1K 1/16W 1% 0402; AGILE_PN: 470-76098; CAD_APPROVED: Yes; FPLIST: RC0402_25,RC0402_HD,0402_CC; HEIGHT: 0.4; MFG_NAME01: BOURNS; MFG_PN01: CR0402-FX-1212GLF; ROHS: Yes; Tolerance: 1%
R84-R89 R91 R92 = RES: RES MF 4.7K 1/16W 5% 0402; AGILE_PN: 470-75626; ASSY_OPT: DNP; CAD_APPROVED: Yes; FPLIST: RC0402_25,RC0402_HD,0402_CC,RC0402_X2; HEIGHT: 0.41; MFG_NAME01: BOURNS; MFG_PN01: CR0402-JW-472GLF; Pkg: 0402; ROHS: NULL; Tolerance: 5%
T1 = SM13072APEL_XFMR16P: XFMR LAN 10/100BASE-TX 1CT:1CT SMT; 3D_Mechanical_Footprint_File: http://fcl.am.freescale.net/ALLEGRO/step/xfmr16_1p27_13p05x7p15.STEP; AGILE_PN: 560-77654; CAD_APPROVED: Yes; HEIGHT: 5.90; MFG_NAME01: BOURNS; Package Size: SMD-16; ROHS: Yes; Temp Range: -40C to +85C
TP22 = TESTLOOP: TEST POINT PAD 40MIL DIA SMT, NO PART TO ORDER; AGILE_PN: 211-10189; CAD_APPROVED: yes; HEIGHT: 0.1MM; MFG_NAME01: NO PART TO ORDER; MFG_PN01: NO PART TO ORDER; ROHS: NULL; SILK: EPHY_VDDA
TP23 = TESTLOOP: TEST POINT PAD 40MIL DIA SMT, NO PART TO ORDER; AGILE_PN: 211-10189; CAD_APPROVED: yes; HEIGHT: 0.1MM; MFG_NAME01: NO PART TO ORDER; MFG_PN01: NO PART TO ORDER; ROHS: NULL; SILK: EPHY_VDDIO
TP24 = TESTLOOP: TEST POINT PAD 30MIL DIA SMT, NO PART TO ORDER; 3D_Mechanical_Footprint_File: http://fcl.am.freescale.net/ALLEGRO/step/tpad_030.STEP; AGILE_PN: 211-76642; CAD_APPROVED: Yes; HEIGHT: 0.1; MFG_NAME01: NOTACOMPONENT; MFG_PN01: NOTACOMPONENT; ROHS: Yes; SILK: INT
TP25 = TESTLOOP: TEST POINT PAD 30MIL DIA SMT, NO PART TO ORDER; 3D_Mechanical_Footprint_File: http://fcl.am.freescale.net/ALLEGRO/step/tpad_030.STEP; AGILE_PN: 211-76642; CAD_APPROVED: Yes; HEIGHT: 0.1; MFG_NAME01: NOTACOMPONENT; MFG_PN01: NOTACOMPONENT; ROHS: Yes; SILK: TXCLK
TP26 = TESTLOOP: TEST POINT PAD 30MIL DIA SMT, NO PART TO ORDER; 3D_Mechanical_Footprint_File: http://fcl.am.freescale.net/ALLEGRO/step/tpad_030.STEP; AGILE_PN: 211-76642; CAD_APPROVED: Yes; HEIGHT: 0.1; MFG_NAME01: NOTACOMPONENT; MFG_PN01: NOTACOMPONENT; ROHS: Yes; SILK: CRS
TP27 = TESTLOOP: TEST POINT PAD 30MIL DIA SMT, NO PART TO ORDER; 3D_Mechanical_Footprint_File: http://fcl.am.freescale.net/ALLEGRO/step/tpad_030.STEP; AGILE_PN: 211-76642; CAD_APPROVED: Yes; HEIGHT: 0.1; MFG_NAME01: NOTACOMPONENT; MFG_PN01: NOTACOMPONENT; ROHS: Yes; SILK: RXDV
TP45 = TESTLOOP: TEST POINT PAD 40MIL DIA SMT, NO PART TO ORDER; AGILE_PN: 211-10189; CAD_APPROVED: yes; HEIGHT: 0.1MM; MFG_NAME01: NO PART TO ORDER; MFG_PN01: NO PART TO ORDER; ROHS: NULL; SILK: EPHY_1V2
U10 = LAN8710: IC XCVR ETHERNET PHY MII/RMII 1.8-3.3V SQFN32; 3D_Mechanical_Footprint_File: http://fcl.am.freescale.net/ALLEGRO/step/qfn32ep.STEP; AGILE_PN: 312-83484; CAD_APPROVED: Yes; HEIGHT: 1; MFG_NAME01: Microchip Technology; Package Size: SQFN-32; ROHS: Yes; Supply Voltage: 1.8-3.3V; Temp Range: -0C to +70C
Y4 = OSC4_KC2520K: OSC 50.000MHZ CLK CMOS 50PPM 1.8V/ 2.5V/ 3.3V SMT; 3D_Mechanical_Footprint_File: http://fcl.am.freescale.net/ALLEGRO/step/osc4_2p6x2p1_sm.STEP; AGILE_PN: 230-10063; CAD_APPROVED: YES; HEIGHT: 0.80mm; MFG_NAME01: KYOCERA; MFG_PN01: KC2520Z50.0000C1GX00; Package Size: 2.5 mm x 2 mm; ROHS: NULL; Temp Range: -40°C to +85°C
C69 C70 C72 C73 C75 C76 = CAP_NP: CAP CER 1.0uF 16V 10% X6S 0402; AGILE_PN: 150-80262; CAD_APPROVED: Yes; FPLIST: CC0402_25,CC0402_HD,0402_CC,capc0402_l; HEIGHT: 0.55; MFG_NAME01: MURATA; MFG_PN01: GRM155C81C105KE11D; ROHS: Yes; Rated Voltage: 16V; SIGNAL_MODEL: DEFAULT_CAPACITOR_1e+06pF_2_1; Temp Range: -55C to +105C; Temp_Range: -55°C to +125°C; Tolerance: 10%; VOLTAGE: 16V
C71 C74 C77 = CAP_NP: CAP CER 0.01UF 50V 10% X7R 0402; AGILE_PN: 150-30114; ASSY_OPT: DNP; CAD_APPROVED: Yes; FPLIST: CC0402_25,CC0402_HD,0402_CC,capc0402_l; HEIGHT: 0.55MM; MFG_NAME01: MURATA; MFG_PN01: GRM155R71H103KA88D; ROHS: NULL; Rated Voltage: 50V; Temp Range: -55C to +125C; Tolerance: 10%
D10-D12 = DIODE_NUP2105L: DIODE DUAL LINE CAN BUS PROTECTOR 27V 350W SOT-23; AGILE_PN: 480-77157; CAD_APPROVED: Yes; HEIGHT: 1.11; MFG_NAME01: ON SEMICONDUCTOR; MFG_PN01: NUP2105LT1G
J17 = CONN_HDR_2X2: HDR 2X2 TH 100MIL CTR 340H SN 105L; AGILE_PN: 210-78429; CAD_APPROVED: Yes; HEIGHT: 8.9; MFG_NAME01: TYCO ELECTRONICS; MFG_PN01: 5-146258-2; ROHS: Yes; SILK: CAN0
J18 = CONN_HDR_2X2: HDR 2X2 TH 100MIL CTR 340H SN 105L; AGILE_PN: 210-78429; CAD_APPROVED: Yes; HEIGHT: 8.9; MFG_NAME01: TYCO ELECTRONICS; MFG_PN01: 5-146258-2; ROHS: Yes; SILK: CAN1
J19 = CONN_HDR_2X2: HDR 2X2 TH 100MIL CTR 340H SN 105L; AGILE_PN: 210-78429; CAD_APPROVED: Yes; HEIGHT: 8.9; MFG_NAME01: TYCO ELECTRONICS; MFG_PN01: 5-146258-2; ROHS: Yes; SILK: CAN2
R93 R99 R105 = RES: RES MF 10K 1/16W 5% 0402; AGILE_PN: 470-75557; ASSY_OPT: DNP; CAD_APPROVED: Yes; FPLIST: RC0402_25,RC0402_HD,0402_CC; HEIGHT: 0.4MM; MFG_NAME01: BOURNS; MFG_PN01: CR0402-JW-103GLF; ROHS: NULL; SIGNAL_MODEL: DEFAULT_RESISTOR_10000OHM_2_1; TOL: 5%; Temp_Range: –55 °C to +155 °C; Tolerance: 5%
R94 R97 R100 R103 R106 R107 = RES: RES MF 62 OHM 1/4W 1% AEC-Q200 0805; 3D_Mechanical_Footprint_File: http://fcl.am.freescale.net/ALLEGRO/step/RC0805_OV.STEP; AGILE_PN: 470-83214; CAD_APPROVED: Yes; FPLIST: RC0805_OV,RC0805,0805_CC; HEIGHT: 0.60; MFG_NAME01: KOA SPEER; MFG_PN01: SG73P2ATTD62R0F; Package Size: 0805 (2012 Metric); ROHS: Yes; Temp Range: -55 °C to +155 °C; Tolerance: 1%
SJ1 SJ2 = RES_3PIN_C: SOLDER BLOB JUMPER 3PIN 1-2 SHORT 0402 - NO PART TO ORDER; AGILE_PN: 470-83592; CAD_APPROVED: Yes; HEIGHT: 0.1016; MFG_NAME01: NA; ROHS: Yes; SHORT(DEFAULT): 1-2
TP28 = TESTLOOP: TEST POINT PAD 40MIL DIA SMT, NO PART TO ORDER; AGILE_PN: 211-10189; CAD_APPROVED: yes; HEIGHT: 0.1MM; MFG_NAME01: NO PART TO ORDER; MFG_PN01: NO PART TO ORDER; ROHS: NULL; SILK: CAN0_H
TP29 = TESTLOOP: TEST POINT PAD 30MIL DIA SMT, NO PART TO ORDER; 3D_Mechanical_Footprint_File: http://fcl.am.freescale.net/ALLEGRO/step/tpad_030.STEP; AGILE_PN: 211-76642; CAD_APPROVED: Yes; HEIGHT: 0.1; MFG_NAME01: NOTACOMPONENT; MFG_PN01: NOTACOMPONENT; ROHS: Yes; SILK: CAN0_RX
TP30 = TESTLOOP: TEST POINT PAD 40MIL DIA SMT, NO PART TO ORDER; AGILE_PN: 211-10189; CAD_APPROVED: yes; HEIGHT: 0.1MM; MFG_NAME01: NO PART TO ORDER; MFG_PN01: NO PART TO ORDER; ROHS: NULL; SILK: CAN0_L
TP31 = TESTLOOP: TEST POINT PAD 40MIL DIA SMT, NO PART TO ORDER; AGILE_PN: 211-10189; CAD_APPROVED: yes; HEIGHT: 0.1MM; MFG_NAME01: NO PART TO ORDER; MFG_PN01: NO PART TO ORDER; ROHS: NULL; SILK: CAN1_H
TP32 = TESTLOOP: TEST POINT PAD 30MIL DIA SMT, NO PART TO ORDER; 3D_Mechanical_Footprint_File: http://fcl.am.freescale.net/ALLEGRO/step/tpad_030.STEP; AGILE_PN: 211-76642; CAD_APPROVED: Yes; HEIGHT: 0.1; MFG_NAME01: NOTACOMPONENT; MFG_PN01: NOTACOMPONENT; ROHS: Yes; SILK: CAN1_RX
TP33 = TESTLOOP: TEST POINT PAD 40MIL DIA SMT, NO PART TO ORDER; AGILE_PN: 211-10189; CAD_APPROVED: yes; HEIGHT: 0.1MM; MFG_NAME01: NO PART TO ORDER; MFG_PN01: NO PART TO ORDER; ROHS: NULL; SILK: CAN1_L
TP34 = TESTLOOP: TEST POINT PAD 40MIL DIA SMT, NO PART TO ORDER; AGILE_PN: 211-10189; CAD_APPROVED: yes; HEIGHT: 0.1MM; MFG_NAME01: NO PART TO ORDER; MFG_PN01: NO PART TO ORDER; ROHS: NULL; SILK: CAN2_H
TP35 = TESTLOOP: TEST POINT PAD 30MIL DIA SMT, NO PART TO ORDER; 3D_Mechanical_Footprint_File: http://fcl.am.freescale.net/ALLEGRO/step/tpad_030.STEP; AGILE_PN: 211-76642; CAD_APPROVED: Yes; HEIGHT: 0.1; MFG_NAME01: NOTACOMPONENT; MFG_PN01: NOTACOMPONENT; ROHS: Yes; SILK: CAN2_RX
TP36 = TESTLOOP: TEST POINT PAD 40MIL DIA SMT, NO PART TO ORDER; AGILE_PN: 211-10189; CAD_APPROVED: yes; HEIGHT: 0.1MM; MFG_NAME01: NO PART TO ORDER; MFG_PN01: NO PART TO ORDER; ROHS: NULL; SILK: CAN2_L
U11-U13 = TJA1051TK_3_HVSON8: IC XCVR CAN 4.5-5.5V AEC-Q100 HVSON8; 3D_Mechanical_Footprint_File: http://fcl.am.freescale.net/ALLEGRO/step/son8_0p65_3p15x3p15.STEP; AGILE_PN: 312-10381; CAD_APPROVED: Yes; HEIGHT: 1mm; MFG_NAME01: NXP Semiconductor; MFG_PN01: TJA1057BTK/0J; Package Size: HVSON-8; ROHS: NULL; Supply Voltage: 4.5 V to 5.5 V
U14 U15 = 74LVCH1T45_6P: IC XCVR XLATING DUAL 3-STATE 1.2- 5.5V XSON6; AGILE_PN: 312-80894; CAD_APPROVED: Yes; HEIGHT: 0.5; MFG_NAME01: NEXPERIA; ROHS: Yes; VOLTAGE: 1.2- 5.5V

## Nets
DGND: C33.2 C34.2 C35.2 C36.2 C37.2 C38.2 C39.2 C40.2 C41.2 C42.2 C43.2 C44.2 C45.2 C46.2 C47.2 C48.2 C49.2 C50.2 C51.2 C52.2 C53.2 C54.2 C56.2 C57.2 C58.2 C59.2 C60.2 C61.2 C62.2 C63.2 C64.2 C65.2 C66.2 C67.2 C68.2 C69.2 C70.2 C71.2 C72.2 C73.2 C74.2 C75.2 C76.2 C77.2 C78.2 C79.2 C80.2 C81.2 D8.A D9.2(A) D10.3(ANODES) D11.3(ANODES) D12.3(ANODES) J13.A1(GND1) J13.A12(GND2) J13.B1(GND4) J13.B12(GND3) J13.SH1 J13.SH2 J13.SH3 J13.SH4 J14.3(A2) J14.5(A3) J15.5 J17.4(B2) J18.4(B2) J19.4(B2) JP3.1 JP4.2 JP5.2 JP6.2 R21.2 R22.2 R23.2 R25.2 R26.2 R30.2 R36.2 R37.2 R40.2 R43.2 R49.2 R52.2 R68.1 R69.1 R70.2 R71.2 R75.2 R77.2 R82.2 R83.2 R84.2 R85.2 R86.2 R91.2 R92.2 R98.2 R104.2 R108.2 R110.2 U3.7(GND) U4.D4(VSS_1) U4.D6(VSS_2) U4.E3(VSSA) U4.F4(VSS_3) U4.F6(VSS_4) U4.H3(USB1_VSS) U4.J6(VSS_DCDC) U5.2(GND) U6.2(GND) U7.2(GND) U8.2(GND) U9.2(GND) U10.33(VSS) U11.2(GND) U11.9(EPAD) U12.2(GND) U12.9(EPAD) U13.2(GND) U13.9(EPAD) U14.2(GND) U15.2(GND) Y3.2 Y3.4 Y4.2(GND) ; also on sheet 3 5 11 12 13
GND_ENET: C55.2 C65.1 J16.S1(SHIELD_1) J16.S2(SHIELD_2) R77.1
P3V3_BOARD: C34.1 C35.1 C36.1 C42.1 C45.1 C47.1 C49.1 C51.1 C66.1 C78.1 C80.1 L3.1 R17.1 R18.1 R19.1 R24.1 R27.1 R66.2 U4.D3(VDDA) U4.D5(VDD_2) U4.E5(VDD_3) U4.F5(VDD_1) U4.G5(USB1_3V3) U4.H7(VBAT_DCDC) U4.H8(VBAT_PMU) U5.1(VCCA) U6.1(VCCA) U7.1(VCCA) U8.1(VCCA) U9.1(VCCA) U14.1(VCCA) U15.1(VCCA) Y4.4(VCC) ; also on sheet 3 11 12 13
P5V0: C70.1 C73.1 C76.1 J17.3(A2) J18.3(A2) J19.3(A2) U11.3(VCC) U12.3(VCC) U13.3(VCC) ; also on sheet 3 13
P5V_MCU_LINK: C33.1 L1.2 R20.1 ; also on sheet 3
VDD_HV_A_MCU_IO_REF: C43.1 C44.1 C46.1 C48.1 C50.1 C52.1 C69.1 C72.1 C75.1 C79.1 C81.1 J15.1 R28.1 R32.1 R33.1 R34.1 R38.1 R41.1 R46.1 R93.1 R99.1 R105.1 R109.1 U5.6(VCCB) U6.6(VCCB) U7.6(VCCB) U8.6(VCCB) U9.6(VCCB) U11.5(VIO) U12.5(VIO) U13.5(VIO) U14.6(VCCB) U15.6(VCCB) ; also on sheet 3 6 12 13
BRG_I2C0_SCL: R47.1 U4.B8(P0_21)
BRG_I2C0_SDA: R50.1 U4.A6(P0_4)
CAN_PHY_RXD: R109.2 SJ2.3 U14.4(B)
CAN_PHY_TXD: SJ1.3 U15.4(B)
DBGIF_CAN_RXD: U4.F7(P1_3) U14.3(A)
DBGIF_CAN_TXD: U4.F9(P1_2) U15.3(A)
DBGIF_DETECT: R35.1 U4.B9(P0_22)
DBGIF_RESET: U4.C4(P0_19) U7.3(A)
DBGIF_RESET_TXEN: R43.1 U4.D9(P0_13) U7.5(DIR)
DBGIF_TCK_SWCLK: U4.J8(P0_0) U5.3(A)
DBGIF_TDI: U4.A1(P0_1) U9.3(A)
DBGIF_TDO_SWO: U4.B6(P0_3) U8.3(A)
DBGIF_TMS_SWDIO: U4.B7(P0_2) U6.3(A)
DBGIF_TMS_SWDIO_TXEN: R40.1 U4.D7(P0_28) U6.5(DIR)
ENET_CON_NC4: J16.4 R53.1
ENET_CON_NC5: J16.5 R55.1
ENET_CON_NC7: J16.7 R61.1
ENET_CON_NC8: J16.8 R63.1
ENET_CON_RXN: J16.6 T1.8(RD-)
ENET_CON_RXP: J16.3 T1.6(RD+)
ENET_CON_TXN: J16.2 T1.3(TD-)
ENET_CON_TXP: J16.1 T1.1(TD+)
ENET_CT1: R64.1 T1.2(CT_1)
ENET_CT2: R65.1 T1.7(CT_2)
ENET_CT3&4: C63.1 R60.2 T1.10(CT_3) T1.15(CT_4)
ENET_LED1/REGOFF: J16.9 R92.1 U10.3(LED1/REGOFF)
ENET_LED2/INTSEL_B: J16.11 R71.1 R91.1 U10.2(LED2/~{INTSEL})
ENET_PHY_RST: C68.1 R81.2 R154.2 U10.19(~{RST})
ENET_PHYAD0: R73.1 R88.1
ENET_PHYAD1: R87.1 U10.7(RXCLK/PHYAD1)
ENET_PHYAD2: R89.1 U10.8(RXD3/PHYAD2)
ENET_RMIISEL: R90.1 U10.9(RXD2/RMIISEL)
ENET_RXN: C62.1 R59.2 T1.9(RX-) U10.30(RXN)
ENET_RXP: C61.1 R58.2 T1.11(RX+) U10.31(RXP)
ENET_TXCLK: R80.2 R153.2
ENET_TXD0: R150.2 U10.22(TXD0)
ENET_TXD1: R151.2 U10.23(TXD1)
ENET_TXEN: R72.1 R152.2
ENET_TXN: C60.1 R57.2 T1.14(TX-) U10.28(TXN)
ENET_TXP: C59.1 R56.2 T1.16(TX+) U10.29(TXP)
EPHY_VDDA: C56.1 C57.1 C58.1 L3.2 R56.1 R57.1 R58.1 R59.1 R60.1 TP22.1(Pin1) U10.1(VDD2A) U10.27(VDD1A)
EPHY_VDDCR_1V2: C53.1 C54.1 TP45.1(Pin1) U10.6(VDDCR)
EPHY_VDDIO: C64.1 R66.1 R67.1 R81.1 R87.2 R88.2 R89.2 R90.2 TP23.1(Pin1) U10.12(VDDIO)
HW_VER_2: R25.1 U4.E7(P1_30)
HW_VER_3: R26.1 U4.B3(P1_4)
HW_VER_6: JP4.1 U4.H9(P0_18)
HW_VER_7: JP5.1 U4.G2(P0_27) U5.5(DIR) U9.5(DIR)
HW_VER_9: JP6.1 U4.A2(P0_7) U15.5(DIR)
MCU_LNK_RX: R44.1 U4.A4(P0_29)
MCU_LNK_TX: R45.1 U4.A9(P0_25)
MCULINK_MCU_USB_VBUS: R20.2 R22.1 U4.G4(USB1_VBUS)
MCULINK_USB_DM: J13.A7(DN1) J13.B7(DN2) U3.1(DM) U4.J4(USB1_DM)
MCULINK_USB_DP: J13.A6(DP1) J13.B6(DP2) U3.2(DP) U4.H4(USB1_DP)
MCULINK_USB_VBUS: J13.A4(VBUS1) J13.A9(VBUS2) J13.B4(VBUS4) J13.B9(VBUS3) L1.1 U3.6(VBUS)
PTA4: D9.6(K5) J14.2(B1) J15.2 R33.2 R39.2 ; also on sheet 4
PTA5: D9.1(K1) J14.10(B5) J15.4 R42.2 ; also on sheet 4 12 13
PTA6: R96.1 ; also on sheet 4
PTA7: R95.1 ; also on sheet 4
PTA10: D9.4(K3) J14.6(B3) R48.2 ; also on sheet 4
PTA11: R101.1 ; also on sheet 4
PTA12: R102.1 ; also on sheet 4
PTB4: R67.2 U10.16(MDIO) ; also on sheet 4
PTB5: U10.17(MDC) ; also on sheet 4
PTC0: R78.1 R86.1 ; also on sheet 4
PTC1: R76.1 R84.1 ; also on sheet 4
PTC2: J21.1 R150.1 ; also on sheet 4 11
PTC3: R154.1 ; also on sheet 4 11
PTC4: D9.5(K4) J14.4(B2) J15.3 R31.2 R36.1 ; also on sheet 4
PTC5: D9.3(K2) J14.8(B4) R34.2 R51.2 ; also on sheet 4
PTC17: R74.1 R85.1 ; also on sheet 4
PTD7: J21.2 R151.1 ; also on sheet 4 11
PTD10: J21.5 ; also on sheet 4 11
PTD11: J21.4 R153.1 ; also on sheet 4 11
PTD12: J21.3 R152.1 ; also on sheet 4 11
PTD13: R50.2 ; also on sheet 4 11 13
PTD14: R47.2 ; also on sheet 4 11 13
PTE3: R45.2 ; also on sheet 5 13
PTE14: R44.2 ; also on sheet 5 13
PTE24: SJ1.1 ; also on sheet 5
PTE25: SJ2.1 ; also on sheet 5
RESETN: R29.2 U4.H2(RESETN)
STATUS: D6.C(CATHODE) JP3.2 R24.2 TP21.1(Pin1) U4.C6(P0_5)
USB_ACTIVE: D5.C(CATHODE) U4.C5(P0_6)
VCOM_ACTIVE: D7.C(CATHODE) U4.B4(P0_30)
N29288: R38.2 R39.1 U6.4(B)
N30272: R41.2 R42.1 U7.4(B)
N16808440: R31.1 U5.4(B)
N17139356: D10.1(CATHODE1) J17.1(A1) R94.1 TP28.1(Pin1) U11.7(CANH)
N17139411: R93.2 R98.1 U11.8(S)
N17139494: D10.2(CATHODE2) J17.2(B1) R97.2 TP30.1(Pin1) U11.6(CANL)
N17536864: J13.A5(CC1) R21.1
N17536868: D5.A(ANODE) R17.2
N17536870: D6.A(ANODE) R18.2
N17536872: D7.A(ANODE) R19.2
N17536900: J13.B5(CC2) R23.1
N17537366: C37.1 L2.1 U4.G6(VDD_PMU)
N17537464: L2.2 U4.H6(LX)
N17537500: C41.1 U4.J2(XTAL32M_P) Y3.1
N17537506: C39.1 R28.2 R30.1 U4.F3(P0_23)
N17537534: C38.1 R27.2 R29.1
N17537583: C40.1 U4.J1(XTAL32M_N) Y3.3
N18062845: D12.1(CATHODE1) J19.1(A1) R106.1 TP34.1(Pin1) U13.7(CANH)
N18062888: SJ1.2 U13.1(TXD)
N18062909: R105.2 R108.1 U13.8(S)
N18063033: SJ2.2 TP35.1(Pin1) U13.4(RXD)
N18063039: D12.2(CATHODE2) J19.2(B1) R107.2 TP36.1(Pin1) U13.6(CANL)
N18063856: D11.1(CATHODE1) J18.1(A1) R100.1 TP31.1(Pin1) U12.7(CANH)
N18063888: R99.2 R104.1 U12.8(S)
N18063993: D11.2(CATHODE2) J18.2(B1) R103.2 TP33.1(Pin1) U12.6(CANL)
N18168741: R46.2 R48.1 U8.4(B)
N18169861: R51.1 R52.1 U9.4(B)
N18170769: J14.1(A1) R32.2
N18170873: D8.C J14.9(A5) R35.2 R37.1
N18191195: R49.1 U8.5(DIR)
N18307969: R96.2 TP29.1(Pin1) U11.4(RXD)
N18308000: R102.2 TP32.1(Pin1) U12.4(RXD)
N18326210: TP24.1(Pin1) U10.18(~{INT}/TXER/TXD4)
N18326309: R68.2 U10.25(TXD3)
N18326312: R69.2 U10.24(TXD2)
N18326469: TP25.1(Pin1) U10.20(TXCLK)
N18326563: R73.2 U10.13(RXER/RXD4/PHYAD0)
N18326577: R72.2 U10.21(TXEN)
N18326609: TP26.1(Pin1) U10.14(CRS)
N18326622: R74.2 U10.15(COL/CRS_DV/MODE2)
N18326681: R78.2 U10.10(RXD1/MODE1)
N18326713: R76.2 U10.11(RXD0/MODE0)
N18326873: TP27.1(Pin1) U10.26(RXDV)
N18327158: C67.1 R82.1 U10.32(RBIAS)
N18327491: R79.1 R80.1 U10.5(XTAL1/CLKIN)
N18347550: C71.1 R94.2 R97.1
N18347800: C74.1 R100.2 R103.1
N18348054: C77.1 R106.2 R107.1
N18494687: R110.1 U14.5(DIR)
N18666556: R95.2 U11.1(TXD)
N18666622: R101.2 U12.1(TXD)
N18782104: R79.2 Y4.3(OUT)
N18785538: J16.10 R70.1
N18785600: J16.12 R75.1
N18786729: C55.1 R54.2 R62.2 R64.2 R65.2
N18786733: R61.2 R62.1 R63.2
N18786737: R53.2 R54.1 R55.2
N19003297: R83.1 Y4.1(INH)

Not connected (* = marked no-connect by the designer): J13 A2(SSTXP1)* A3(SSTXN1)* A8(SBU1)* A10(SSRXN2)* A11(SSRXP2)* B2(SSTXP2)* B3(SSTXN2)* B8(SBU2)* B10(SSRXN1)* B11(SSRXP1)*; J14 7(A4)*; T1 4(NC_1)* 5(NC_2)* 12(NC_3)* 13(NC_4)*; U3 3(USB_ID)* 4(NC1)* 5(NC2)*; U4 A8(P1_29)* B1(P0_17)* B2(P1_0)* C2(P0_12)* C8(P0_20)* D1(P0_16)* D2(P0_11)* D8(P0_14)* F1(P0_10)* F2(P0_15)* F8(P0_26)* G8(P1_1)* H1(P0_8)* J9(P0_9)*; U10 4(XTAL2)*

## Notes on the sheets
sheet 7
- USB
- STATUS LED
- BOOT MODE
- MCU
- Note:
  Open  : Boot from Internal Flash
  Closed: Enable ISP mode (USB1)
- HARDWARE VERSION
- DBGIF_ISP0_CTRL
- DBGIF_CAN_S
- HW_VER_2: USB-SIO bridge disable when low
  HW_VER_3: OB selection when low
  HW_VER_6: VCOM disable when low
  HW_VER_7: SWD disable when low
  HW_VER_9: USB to CAN disable when low
sheet 8
- MCU-Link Debug Interface
- MCU SWD/JTAG
- SWDIO/TMS
- TMS/SWDIO
- DIR#  L: B to A, H: A to B
- SWDCLK/TCK
- TCLK/SWCLK
- SWO/TDO
- TDI
- TDI
- TDO/SWO
- nRST
- RESET
- DIR#  L: B to A, H: A to B
- DIR#  L: B to A, H: A to B
- SIO BRIDGE
- DIR#  L: B to A, H: A to B
- DIR#  L: B to A, H: A to B
sheet 9
- ETHERNET
- Layout note:
  ======
  Place R56~R59 close to U10
- Note:
  REGOFF=1(External PU, Regulator OFF), LED1 output=Active Low;
  REGOFF=0(Internal PD, Regulator ON), LED1 output=Active High.(Default)
  /INTSEL=1(Internal PU), LED2 output=Active Low;
  /INTSEL=0(External PD), LED2 output=Active High.(Default)
- Layout note:
  ======
  Differential 100ohm
  Difference tolerance 100mil
- TXD3/2 pins must be grounded in RMII mode.
- TX+
- TX-
- RX+
- NC
- NC
- RX-
- NC
- NC
- INH=High/OPEN: Enable
  INH=Low: Disable
- Layout note:
  ======
  GND_ENET is a small isolated
  GND plane which should extend
  under RJ45 connector
- Config Pin (Internal State)
- Description
- Jumper Setting
- Mode Config
  111 => All Capable, auto-neg enabled (Default)
- MODE[0:2] (PU)
- Open (Int PU)
- Device Address
  000 => Default
- PHYAD[0:2] (PD)
- Open (Int PU)
- RMIISEL (PD)
- 1 => RMII (Default)
  0=> MII
- Closed (Ext PU)
- 1 => Internal Regulator OFF
  0/Floating=> Internal Regulator ON (Default)
- REGOFF (PD)
- Open (Int PU)
- INTSEL_B (PU)
- Floating 1 => nINT function  (Default)
  0=> TXD4/TXER function
- Open (Int PU)
sheet 10
- MAX 70 mA @5V
- CAN0
- MAX 70 mA @5V
- CAN1
- MAX 70 mA @5V
- CAN2
- DIR#  L: B to A
  H: A to B
- DIR#  L: B to A
  H: A to B
